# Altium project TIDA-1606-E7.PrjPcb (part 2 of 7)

## Sheet TIDA-1606-EMI-Protection-E7-.SchDoc
size 431 x 279 mm; Date: Not shown in title block; ApprovedBy: Not shown in title block; CheckedBy: Not shown in title block; Author: Not shown in title block; CompanyName: Not shown in title block; Engineer: Not shown in title block; Organization: Not shown in title block; Address1: Not shown in title block; Address2: Not shown in title block; Address3: Not shown in title block; Address4: Not shown in title block; DocumentNumber: 4; Revision: Use project parameter SCH_Rev; SheetNumber: 4; SheetTotal: 16; PageSetup: Record=PageOptions¦CenterHorizontal=True¦CenterVertical=True¦PrintScale=1.00¦XCorrection=1.00¦YCorrection=1.00¦PrintKind=0¦BorderSize=5000000¦LeftOffset=0¦BottomOffset=0¦Orientation=2¦PaperLength=1000¦PaperWidth=1000¦Scale=100¦PaperSource=15¦PrintQuality=600¦MediaType=1¦DitherType=10¦PaperKind=Letter¦PrintScaleMode=1
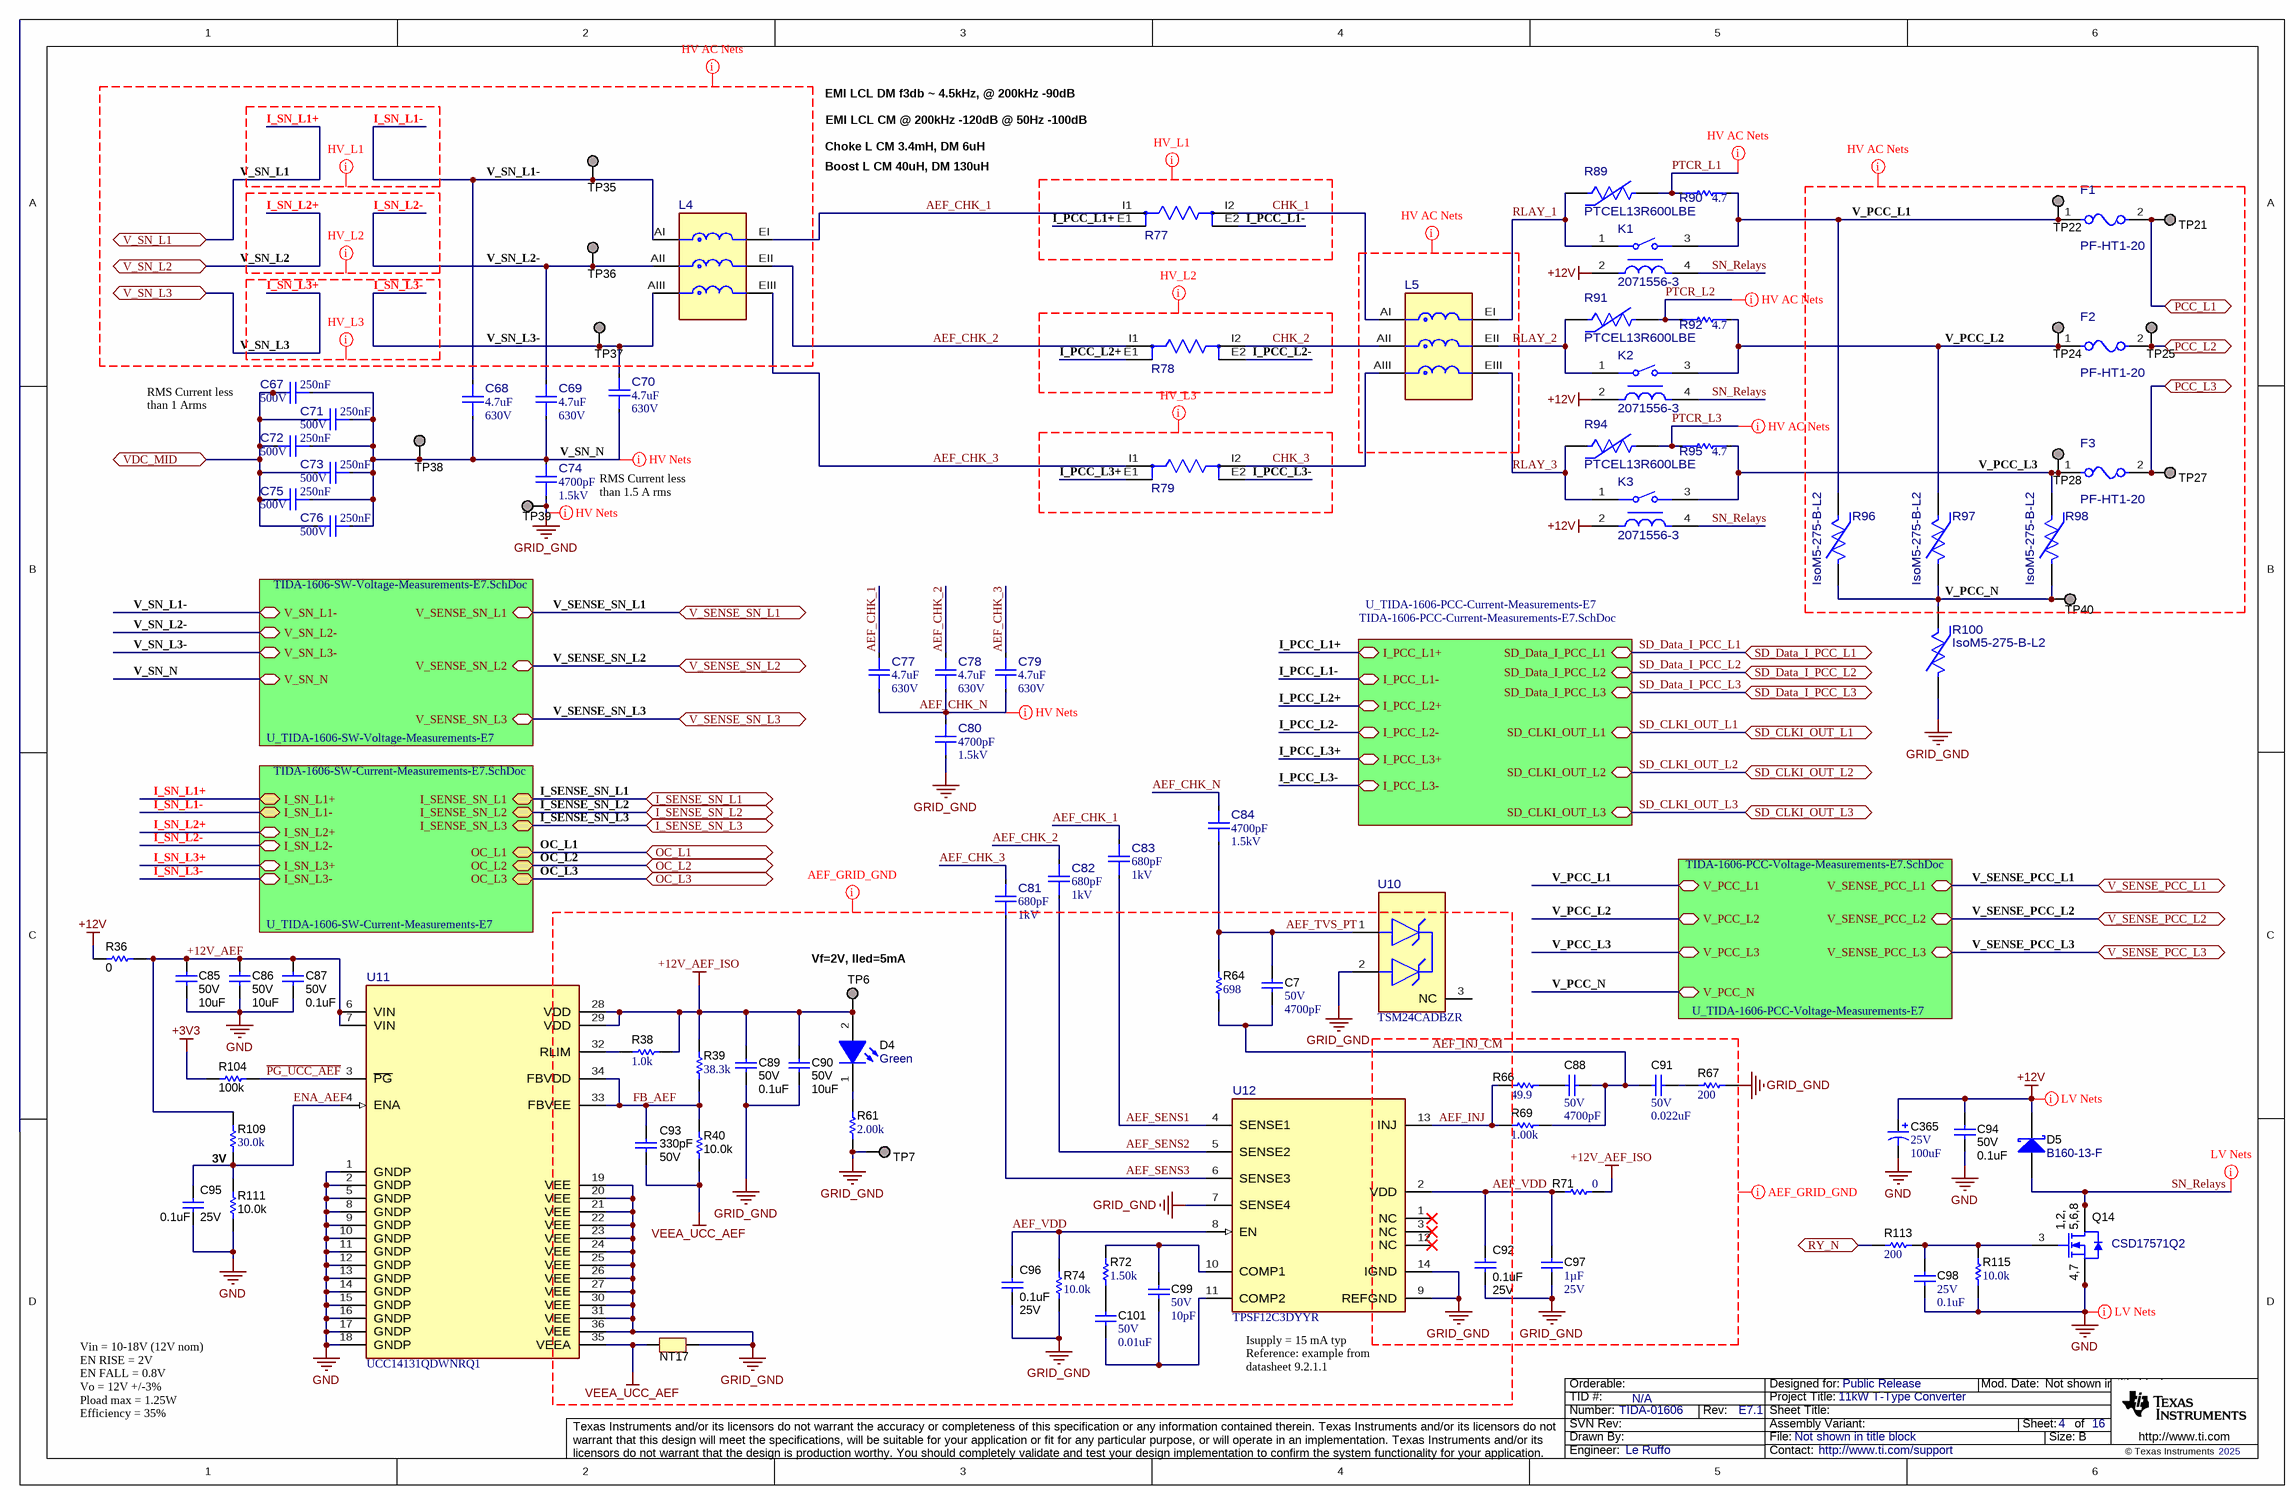
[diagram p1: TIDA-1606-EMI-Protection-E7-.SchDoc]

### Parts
C7  VDC_V: 50V  ValueDisplayed: 4700pF  [0402]  (hidden comment: GRM155R71H472KA01D)
C67  ValueDisplayed: 250nF  VDC_V: 500V  [FP-B58043E5254M052_2220-MFG]  (hidden comment: B58043E5254M052)
C68  ValueDisplayed: 4.7uF  VDC_V: 630V  [FP-R523R447050P1M_RADIAL-MFG]  (hidden comment: R523R447050P1M)
C69  ValueDisplayed: 4.7uF  VDC_V: 630V  [FP-R523R447050P1M_RADIAL-MFG]  (hidden comment: R523R447050P1M)
C70  ValueDisplayed: 4.7uF  VDC_V: 630V  [FP-R523R447050P1M_RADIAL-MFG]  (hidden comment: R523R447050P1M)
C71  ValueDisplayed: 250nF  VDC_V: 500V  [FP-B58043E5254M052_2220-MFG]  (hidden comment: B58043E5254M052)
C72  ValueDisplayed: 250nF  VDC_V: 500V  [FP-B58043E5254M052_2220-MFG]  (hidden comment: B58043E5254M052)
C73  ValueDisplayed: 250nF  VDC_V: 500V  [FP-B58043E5254M052_2220-MFG]  (hidden comment: B58043E5254M052)
C74  ValueDisplayed: 4700pF  VDC_V: 1.5kV  [FP-R413F147050T1K_RADIAL-MFG]  (hidden comment: R413F147050T1K)
C75  ValueDisplayed: 250nF  VDC_V: 500V  [FP-B58043E5254M052_2220-MFG]  (hidden comment: B58043E5254M052)
C76  ValueDisplayed: 250nF  VDC_V: 500V  [FP-B58043E5254M052_2220-MFG]  (hidden comment: B58043E5254M052)
C77  ValueDisplayed: 4.7uF  VDC_V: 630V  [FP-R523R447050P1M_RADIAL-MFG]  (hidden comment: R523R447050P1M)
C78  ValueDisplayed: 4.7uF  VDC_V: 630V  [FP-R523R447050P1M_RADIAL-MFG]  (hidden comment: R523R447050P1M)
C79  ValueDisplayed: 4.7uF  VDC_V: 630V  [FP-R523R447050P1M_RADIAL-MFG]  (hidden comment: R523R447050P1M)
C80  ValueDisplayed: 4700pF  VDC_V: 1.5kV  [FP-R413F147050T1K_RADIAL-MFG]  (hidden comment: R413F147050T1K)
C81  ValueDisplayed: 680pF  VDC_V: 1kV  [FP-DK1B3EA681K86RBH01_SMD2-MFG]  (hidden comment: DK1B3EA681K86RBH01)
C82  ValueDisplayed: 680pF  VDC_V: 1kV  [FP-DK1B3EA681K86RBH01_SMD2-MFG]  (hidden comment: DK1B3EA681K86RBH01)
C83  ValueDisplayed: 680pF  VDC_V: 1kV  [FP-DK1B3EA681K86RBH01_SMD2-MFG]  (hidden comment: DK1B3EA681K86RBH01)
C84  ValueDisplayed: 4700pF  VDC_V: 1.5kV  [FP-EVA86Q7UTF472KA01K_SMD2-MFG]  (hidden comment: EVA86Q7UTF472KA01K)
C85  VDC_V: 50V  ValueDisplayed: 10uF  [1206_180L]  (hidden comment: CL31B106KBHNNNE)
C86  VDC_V: 50V  ValueDisplayed: 10uF  [1206_180L]  (hidden comment: CL31B106KBHNNNE)
C87  VDC_V: 50V  ValueDisplayed: 0.1uF  [0402S]  (hidden comment: GCM155R71H104KE02D)
C88  VDC_V: 50V  ValueDisplayed: 4700pF  [0402]  (hidden comment: GRM155R71H472KA01D)
C89  VDC_V: 50V  ValueDisplayed: 0.1uF  [0402S]  (hidden comment: GCM155R71H104KE02D)
C90  VDC_V: 50V  ValueDisplayed: 10uF  [1206_180L]  (hidden comment: CL31B106KBHNNNE)
C91  VDC_V: 50V  ValueDisplayed: 0.022uF  [0402]  (hidden comment: GRM155R71H223KA12D)
C92  VDC_V: 25V  ValueDisplayed: 0.1uF  [0402S]  (hidden comment: GRM155R71E104KE14D)
C93  VDC_V: 50V  ValueDisplayed: 330pF  [0402S]  (hidden comment: CGA2B2X7R1H331K050BA)
C94  VDC_V: 50V  ValueDisplayed: 0.1uF  [0402S]  (hidden comment: GCM155R71H104KE02D)
C95  VDC_V: 25V  ValueDisplayed: 0.1uF  [0402S]  (hidden comment: GRM155R71E104KE14D)
C96  VDC_V: 25V  ValueDisplayed: 0.1uF  [0402S]  (hidden comment: GRM155R71E104KE14D)
C97  Cap_F: 1µF  VDC_V: 25V  [0603]  (hidden comment: CGA3E1X7R1E105M080AC)
C98  VDC_V: 25V  ValueDisplayed: 0.1uF  [0402]  (hidden comment: GRM155R71E104KE14D)
C99  VDC_V: 50V  ValueDisplayed: 10pF  [0402]  (hidden comment: CGA2B2C0G1H100D050BA)
C101  VDC_V: 50V  ValueDisplayed: 0.01uF  [0402]  (hidden comment: CGA2B3X7R1H103K050BB)
C365  VDC_V: 25V  ValueDisplayed: 100uF  [FM_630x1120]  (hidden comment: EEU-FM1E101)
D4  value Green  [WL-SMCW_GREEN]  (hidden comment: 150060VS75000)
D5  B160-13-F  [SMA]
F1  PF-HT1-20  [FP-PF-HT1-20_PTH_FUSE_38MM0_10MM3-MFG]
F2  PF-HT1-20  [FP-PF-HT1-20_PTH_FUSE_38MM0_10MM3-MFG]
F3  PF-HT1-20  [FP-PF-HT1-20_PTH_FUSE_38MM0_10MM3-MFG]
K1  2071556-3  [FP-2071556-3_PTH_RELAY_18MM2_10MM2-MFG]
K2  2071556-3  [FP-2071556-3_PTH_RELAY_18MM2_10MM2-MFG]
K3  2071556-3  [FP-2071556-3_PTH_RELAY_18MM2_10MM2-MFG]
L4  WK 3260A  [FP-WK 3260A_PTH6_41MM5_43MM5-MFG]  (value not drawn)
L5  WK 3260A  [FP-WK 3260A_PTH6_41MM5_43MM5-MFG]  (value not drawn)
NT17  Net-Tie  [Net-Tie7milsWide_20milsLong]  (value not drawn)  (net tie, no BOM)
Q14  CSD17571Q2  [DQK0006C]
R36  ValueDisplayed: 0  [0603L]  (hidden comment: RCS06030000Z0EA)
R38  ValueDisplayed: 1.0k  [0402]  (hidden comment: ERJ-2GEJ102X)
R39  ValueDisplayed: 38.3k  [0402]  (hidden comment: CRCW040238K3FKED)
R40  ValueDisplayed: 10.0k  [0402S]  (hidden comment: MCS0402MD1002BE100)
R61  ValueDisplayed: 2.00k  [0402]  (hidden comment: ERJ-2RKF2001X)
R64  ValueDisplayed: 698  [0402]  (hidden comment: ERJ-2RKF6980X)
R66  ValueDisplayed: 49.9  [0402L]  (hidden comment: ERJ-2RKF49R9X)
R67  ValueDisplayed: 200  [0402]  (hidden comment: CRCW0402200RJNED)
R69  ValueDisplayed: 1.00k  [0402]  (hidden comment: ERJ-2RKF1001X)
R71  ValueDisplayed: 0  [0402L]  (hidden comment: RC0402JR-070RL)
R72  ValueDisplayed: 1.50k  [0402]  (hidden comment: ERJ-2RKF1501X)
R74  ValueDisplayed: 10.0k  [0402]  (hidden comment: CRCW040210K0FKED)
R77  WSKW06122L000FEA  [FP-WSKW06122L000FEA_0612-MFG]  (value not drawn)
R78  WSKW06122L000FEA  [FP-WSKW06122L000FEA_0612-MFG]  (value not drawn)
R79  WSKW06122L000FEA  [FP-WSKW06122L000FEA_0612-MFG]  (value not drawn)
R89  PTCEL13R600LBE  [FP-PTCEL13R600LBE_RADIAL-MFG]
R90  value 4.7  [FP-UPR25J4R7CT_2512-MFG]  (hidden comment: UPR25J4R7CT)
R91  PTCEL13R600LBE  [FP-PTCEL13R600LBE_RADIAL-MFG]
R92  value 4.7  [FP-UPR25J4R7CT_2512-MFG]  (hidden comment: UPR25J4R7CT)
R94  PTCEL13R600LBE  [FP-PTCEL13R600LBE_RADIAL-MFG]
R95  value 4.7  [FP-UPR25J4R7CT_2512-MFG]  (hidden comment: UPR25J4R7CT)
R96  IsoM5-275-B-L2  [FP-IsoM5-275-B-L2_RADIAL-MFG]
R97  IsoM5-275-B-L2  [FP-IsoM5-275-B-L2_RADIAL-MFG]
R98  IsoM5-275-B-L2  [FP-IsoM5-275-B-L2_RADIAL-MFG]
R100  IsoM5-275-B-L2  [FP-IsoM5-275-B-L2_RADIAL-MFG]
R104  ValueDisplayed: 100k  [0402S]  (hidden comment: ERJ-2GEJ104X)
R109  ValueDisplayed: 30.0k  [0402]  (hidden comment: CRCW040230K0FKED)
R111  ValueDisplayed: 10.0k  [0402S]  (hidden comment: MCS0402MD1002BE100)
R113  ValueDisplayed: 200  [0402]  (hidden comment: CRCW0402200RJNED)
R115  ValueDisplayed: 10.0k  [0402]  (hidden comment: CRCW040210K0FKED)
TP6  TP_SM_1MM  [TP_SM_1MM]  (value not drawn)  (no BOM)
TP7  S2751-46R  [Harwin_S2751-46R]  (value not drawn)
TP21  S2751-46R  [Harwin_S2751-46R]  (value not drawn)
TP22  S2751-46R  [Harwin_S2751-46R]  (value not drawn)
TP24  S2751-46R  [Harwin_S2751-46R]  (value not drawn)
TP25  S2751-46R  [Harwin_S2751-46R]  (value not drawn)
TP27  S2751-46R  [Harwin_S2751-46R]  (value not drawn)
TP28  S2751-46R  [Harwin_S2751-46R]  (value not drawn)
TP35  S2751-46R  [Harwin_S2751-46R]  (value not drawn)
TP36  S2751-46R  [Harwin_S2751-46R]  (value not drawn)
TP37  S2751-46R  [Harwin_S2751-46R]  (value not drawn)
TP38  S2751-46R  [Harwin_S2751-46R]  (value not drawn)
TP39  S2751-46R  [Harwin_S2751-46R]  (value not drawn)
TP40  S2751-46R  [Harwin_S2751-46R]  (value not drawn)
U10  TSM24CADBZR  [DBZ0003A-MFG]
U11  UCC14131QDWNRQ1  [DWJ0036A-MFG]
U12  TPSF12C3DYYR  [DYY0014A-MFG]

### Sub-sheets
U_TIDA-1606-PCC-Current-Measurements-E7 = TIDA-1606-PCC-Current-Measurements-E7.SchDoc: I_PCC_L1+ (bidir), I_PCC_L1- (bidir), I_PCC_L2+ (bidir), I_PCC_L2- (bidir), I_PCC_L3+ (bidir), I_PCC_L3- (bidir), SD_Data_I_PCC_L1 (bidir), SD_Data_I_PCC_L2 (bidir), SD_Data_I_PCC_L3 (bidir), SD_CLKI_OUT_L1 (bidir), SD_CLKI_OUT_L2 (bidir), SD_CLKI_OUT_L3 (bidir)
U_TIDA-1606-PCC-Voltage-Measurements-E7 = TIDA-1606-PCC-Voltage-Measurements-E7.SchDoc: V_PCC_L1 (bidir), V_PCC_N (bidir), V_PCC_L2 (bidir), V_PCC_L3 (bidir), V_SENSE_PCC_L1 (bidir), V_SENSE_PCC_L2 (bidir), V_SENSE_PCC_L3 (bidir)
U_TIDA-1606-SW-Current-Measurements-E7 = TIDA-1606-SW-Current-Measurements-E7.SchDoc: I_SENSE_SN_L1 (bidir), I_SENSE_SN_L2 (bidir), I_SENSE_SN_L3 (bidir), I_SN_L1+ (bidir), I_SN_L1- (bidir), I_SN_L2+ (bidir), I_SN_L2- (bidir), I_SN_L3+ (bidir), I_SN_L3- (bidir), OC_L1 (bidir), OC_L2 (bidir), OC_L3 (bidir)
U_TIDA-1606-SW-Voltage-Measurements-E7 = TIDA-1606-SW-Voltage-Measurements-E7.SchDoc: V_SN_L1- (bidir), V_SN_N (bidir), V_SN_L2- (bidir), V_SN_L3- (bidir), V_SENSE_SN_L1 (bidir), V_SENSE_SN_L2 (bidir), V_SENSE_SN_L3 (bidir)

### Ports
I_SENSE_SN_L1 (bidir), I_SENSE_SN_L2 (bidir), I_SENSE_SN_L3 (bidir), OC_L1 (bidir), OC_L2 (bidir), OC_L3 (bidir), PCC_L1 (bidir), PCC_L2 (bidir), PCC_L3 (bidir), RY_N (bidir), SD_CLKI_OUT_L1 (bidir), SD_CLKI_OUT_L2 (bidir), SD_CLKI_OUT_L3 (bidir), SD_Data_I_PCC_L1 (bidir), SD_Data_I_PCC_L2 (bidir), SD_Data_I_PCC_L3 (bidir), V_SENSE_PCC_L1 (bidir), V_SENSE_PCC_L2 (bidir), V_SENSE_PCC_L3 (bidir), V_SENSE_SN_L1 (bidir), V_SENSE_SN_L2 (bidir), V_SENSE_SN_L3 (bidir), V_SN_L1 (bidir), V_SN_L2 (bidir), V_SN_L3 (bidir), VDC_MID (bidir)

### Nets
+3V3: R104.1
+12V: C94.1 C365.1(+) D5.1(K) K1.2 K2.2 K3.2 R36.2
+12V_AEF_ISO: C89.1 C90.1 D4.2(A) R38.2 R39.2 R71.2 TP6.1 U11.28(VDD) U11.29(VDD)
GND: C85.2 C86.2 C87.2 C94.2 C95.2 C98.2 C365.2(-) Q14.4(S) Q14.7(S) R111.1 R115.1 U11.1(GNDP) U11.2(GNDP) U11.5(GNDP) U11.8(GNDP) U11.9(GNDP) U11.10(GNDP) U11.11(GNDP) U11.12(GNDP) U11.13(GNDP) U11.14(GNDP) U11.15(GNDP) U11.16(GNDP) U11.17(GNDP) U11.18(GNDP)
GRID_GND: C74.1 C80.1 C89.2 C90.2 C92.2 C96.2 C97.2 NT17.1 R61.1 R67.2 R74.1 R100.1 TP7.1 TP39.1 U10.2(2_IO) U11.19(VEE) U11.20(VEE) U11.21(VEE) U11.22(VEE) U11.23(VEE) U11.24(VEE) U11.25(VEE) U11.26(VEE) U11.27(VEE) U11.30(VEE) U11.31(VEE) U11.36(VEE) U12.7(SENSE4) U12.9(REFGND) U12.14(IGND)
VDC_MID: C67.2 C71.2 C72.2 C73.2 C75.2 C76.2 ; port VDC_MID
VEEA_UCC_AEF: C93.2 NT17.2 R40.1 U11.35(VEEA)
+12V_AEF: C85.1 C86.1 C87.1 R36.1 R109.2 U11.6(VIN) U11.7(VIN)
~{PG_UCC_AEF}: R104.2 U11.3(~{PG})
AEF_CHK_1: C77.2 C83.2 L4.EI R77.I1
AEF_CHK_2: C78.2 C82.2 L4.EII R78.I1
AEF_CHK_3: C79.2 C81.2 L4.EIII R79.I1
AEF_CHK_N: C77.1 C78.1 C79.1 C80.2 C84.2
AEF_INJ: R66.1 R69.1 U12.13(INJ)
AEF_INJ_CM: C7.2 C88.2 C91.2 R64.1 R69.2
AEF_SENS1: C83.1 U12.4(SENSE1)
AEF_SENS2: C82.1 U12.5(SENSE2)
AEF_SENS3: C81.1 U12.6(SENSE3)
AEF_TVS_PT: C7.1 C84.1 R64.2 U10.1(1_IO)
AEF_VDD: C92.1 C96.1 C97.1 R71.1 R74.2 U12.2(VDD) U12.8(EN)
CHK_1: L5.AI R77.I2
CHK_2: L5.AII R78.I2
CHK_3: L5.AIII R79.I2
ENA_AEF: C95.1 R109.1 R111.2 U11.4(ENA)
FB_AEF: C93.1 R39.1 R40.2 U11.33(FBVEE) U11.34(FBVDD)
I_PCC_L1+: R77.E1 ; sheet U_TIDA-1606-PCC-Current-Measurements-E7/I_PCC_L1+
I_PCC_L1-: R77.E2 ; sheet U_TIDA-1606-PCC-Current-Measurements-E7/I_PCC_L1-
I_PCC_L2+: R78.E1 ; sheet U_TIDA-1606-PCC-Current-Measurements-E7/I_PCC_L2+
I_PCC_L2-: R78.E2 ; sheet U_TIDA-1606-PCC-Current-Measurements-E7/I_PCC_L2-
I_PCC_L3+: R79.E1 ; sheet U_TIDA-1606-PCC-Current-Measurements-E7/I_PCC_L3+
I_PCC_L3-: R79.E2 ; sheet U_TIDA-1606-PCC-Current-Measurements-E7/I_PCC_L3-
I_SENSE_SN_L1: port I_SENSE_SN_L1, sheet U_TIDA-1606-SW-Current-Measurements-E7/I_SENSE_SN_L1
I_SENSE_SN_L2: port I_SENSE_SN_L2, sheet U_TIDA-1606-SW-Current-Measurements-E7/I_SENSE_SN_L2
I_SENSE_SN_L3: port I_SENSE_SN_L3, sheet U_TIDA-1606-SW-Current-Measurements-E7/I_SENSE_SN_L3
I_SN_L1+: port V_SN_L1, sheet U_TIDA-1606-SW-Current-Measurements-E7/I_SN_L1+  [also labelled V_SN_L1]
I_SN_L1-: C68.2 L4.AI TP35.1 ; sheet U_TIDA-1606-SW-Voltage-Measurements-E7/V_SN_L1-, sheet U_TIDA-1606-SW-Current-Measurements-E7/I_SN_L1-  [also labelled V_SN_L1-]
I_SN_L2+: port V_SN_L2, sheet U_TIDA-1606-SW-Current-Measurements-E7/I_SN_L2+  [also labelled V_SN_L2]
I_SN_L2-: C69.2 L4.AII TP36.1 ; sheet U_TIDA-1606-SW-Voltage-Measurements-E7/V_SN_L2-, sheet U_TIDA-1606-SW-Current-Measurements-E7/I_SN_L2-  [also labelled V_SN_L2-]
I_SN_L3+: port V_SN_L3, sheet U_TIDA-1606-SW-Current-Measurements-E7/I_SN_L3+  [also labelled V_SN_L3]
I_SN_L3-: C70.2 L4.AIII TP37.1 ; sheet U_TIDA-1606-SW-Voltage-Measurements-E7/V_SN_L3-, sheet U_TIDA-1606-SW-Current-Measurements-E7/I_SN_L3-  [also labelled V_SN_L3-]
OC_L1: port OC_L1, sheet U_TIDA-1606-SW-Current-Measurements-E7/OC_L1
OC_L2: port OC_L2, sheet U_TIDA-1606-SW-Current-Measurements-E7/OC_L2
OC_L3: port OC_L3, sheet U_TIDA-1606-SW-Current-Measurements-E7/OC_L3
PCC_L1: F1.2 TP21.1 ; port PCC_L1
PCC_L2: F2.2 TP25.1 ; port PCC_L2
PCC_L3: F3.2 TP27.1 ; port PCC_L3
PTCR_L1: R89.2 R90.1
PTCR_L2: R91.2 R92.1
PTCR_L3: R94.2 R95.1
RLAY_1: K1.1 L5.EI R89.1
RLAY_2: K2.1 L5.EII R91.1
RLAY_3: K3.1 L5.EIII R94.1
RY_N: R113.1 ; port RY_N
SD_CLKI_OUT_L1: port SD_CLKI_OUT_L1, sheet U_TIDA-1606-PCC-Current-Measurements-E7/SD_CLKI_OUT_L1
SD_CLKI_OUT_L2: port SD_CLKI_OUT_L2, sheet U_TIDA-1606-PCC-Current-Measurements-E7/SD_CLKI_OUT_L2
SD_CLKI_OUT_L3: port SD_CLKI_OUT_L3, sheet U_TIDA-1606-PCC-Current-Measurements-E7/SD_CLKI_OUT_L3
SD_Data_I_PCC_L1: port SD_Data_I_PCC_L1, sheet U_TIDA-1606-PCC-Current-Measurements-E7/SD_Data_I_PCC_L1
SD_Data_I_PCC_L2: port SD_Data_I_PCC_L2, sheet U_TIDA-1606-PCC-Current-Measurements-E7/SD_Data_I_PCC_L2
SD_Data_I_PCC_L3: port SD_Data_I_PCC_L3, sheet U_TIDA-1606-PCC-Current-Measurements-E7/SD_Data_I_PCC_L3
SN_Relays: D5.2(A) K1.4 K2.4 K3.4 Q14.1(D) Q14.2(D) Q14.5(D) Q14.6(D) Q14.8(D)
V_PCC_L1: F1.1 K1.3 R90.2 R96.2 TP22.1 ; sheet U_TIDA-1606-PCC-Voltage-Measurements-E7/V_PCC_L1
V_PCC_L2: F2.1 K2.3 R92.2 R97.2 TP24.1 ; sheet U_TIDA-1606-PCC-Voltage-Measurements-E7/V_PCC_L2
V_PCC_L3: F3.1 K3.3 R95.2 R98.2 TP28.1 ; sheet U_TIDA-1606-PCC-Voltage-Measurements-E7/V_PCC_L3
V_PCC_N: R96.1 R97.1 R98.1 R100.2 TP40.1 ; sheet U_TIDA-1606-PCC-Voltage-Measurements-E7/V_PCC_N
V_SENSE_PCC_L1: port V_SENSE_PCC_L1, sheet U_TIDA-1606-PCC-Voltage-Measurements-E7/V_SENSE_PCC_L1
V_SENSE_PCC_L2: port V_SENSE_PCC_L2, sheet U_TIDA-1606-PCC-Voltage-Measurements-E7/V_SENSE_PCC_L2
V_SENSE_PCC_L3: port V_SENSE_PCC_L3, sheet U_TIDA-1606-PCC-Voltage-Measurements-E7/V_SENSE_PCC_L3
V_SENSE_SN_L1: port V_SENSE_SN_L1, sheet U_TIDA-1606-SW-Voltage-Measurements-E7/V_SENSE_SN_L1
V_SENSE_SN_L2: port V_SENSE_SN_L2, sheet U_TIDA-1606-SW-Voltage-Measurements-E7/V_SENSE_SN_L2
V_SENSE_SN_L3: port V_SENSE_SN_L3, sheet U_TIDA-1606-SW-Voltage-Measurements-E7/V_SENSE_SN_L3
V_SN_N: C67.1 C68.1 C69.1 C70.1 C71.1 C72.1 C73.1 C74.2 C75.1 C76.1 TP38.1 ; sheet U_TIDA-1606-SW-Voltage-Measurements-E7/V_SN_N
NetC88_1: C88.1 R66.2
NetC91_1: C91.1 R67.1
NetC98_1: C98.1 Q14.3(G) R113.2 R115.2
NetC99_1: C99.1 R72.2 U12.10(COMP1)
NetC99_2: C99.2 C101.2 U12.11(COMP2)
NetC101_1: C101.1 R72.1
NetD4_1: D4.1(K) R61.2
NetR38_1: R38.1 U11.32(RLIM)

Not connected (* = marked no-connect by the designer): U10 3(NC); U12 1(NC)* 3(NC)* 12(NC)*

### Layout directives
net class HV_Nets; net class HV_AC1: AEF_CHK_N, GRID_GND, V_SN_N
net class HV_AC1: I_SN_L1+, I_SN_L1-, I_SN_L2+, I_SN_L2-, I_SN_L3+, I_SN_L3-, PTCR_L1, PTCR_L2, PTCR_L3, RLAY_2, V_SN_L1, V_SN_L1-, V_SN_L2, V_SN_L2-, V_SN_L3, V_SN_L3-
net class HV_L1: CHK_1, I_PCC_L1+, I_PCC_L1-, I_SN_L1+, I_SN_L1-, I_SN_L2+, I_SN_L2-, I_SN_L3+, I_SN_L3-, V_SN_L1, V_SN_L1-, V_SN_L2, V_SN_L2-, V_SN_L3, V_SN_L3-
net class HV_AC1; net class HV_Nets: V_PCC_L1, V_PCC_L2, V_PCC_L3, V_PCC_N
net class LV Nets: +12V, GND, SN_Relays
net class HV_L2: CHK_2, I_PCC_L2+, I_PCC_L2-, I_SN_L1+, I_SN_L1-, I_SN_L2+, I_SN_L2-, I_SN_L3+, I_SN_L3-, V_SN_L1, V_SN_L1-, V_SN_L2, V_SN_L2-, V_SN_L3, V_SN_L3-
net class HV_L3: CHK_3, I_PCC_L3+, I_PCC_L3-, I_SN_L1+, I_SN_L1-, I_SN_L2+, I_SN_L2-, I_SN_L3+, I_SN_L3-, V_SN_L1, V_SN_L1-, V_SN_L2, V_SN_L2-, V_SN_L3, V_SN_L3-
net class AEF_GRID_GND; net class HV_AC1: +12V_AEF_ISO, AEF_INJ, AEF_INJ_CM, AEF_SENS1, AEF_SENS2, AEF_SENS3, AEF_TVS_PT, AEF_VDD, FB_AEF, GRID_GND, VEEA_UCC_AEF

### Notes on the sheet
- EMI LCL DM f3db ~ 4.5kHz, @ 200kHz -90dB
- Choke L CM 3.4mH, DM 6uH
- Boost L CM 40uH, DM 130uH
- EMI LCL CM @ 200kHz -120dB @ 50Hz -100dB
- RMS Current less than 1 Arms
- RMS Current less than 1.5 A rms
- (near TP6) Vf=2V, Iled=5mA
- (near R109) 3V
- Vin = 10-18V (12V nom)
  EN RISE = 2V
  EN FALL = 0.8V
  Vo = 12V +/-3%
  Pload max = 1.25W
  Efficiency = 35%
- (near U12) Isupply = 15 mA typ
  Reference: example from datasheet 9.2.1.1

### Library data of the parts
C7 C88 = CMP-0006692-2: CAP, CERM, 4700 pF, 50 V, +/- 10%, X7R, 0402; Manufacturer: MuRata; TaMin_C: -55°C; Polarized: N; SizeAreaWB_mm2: 3; Value1: Unknown; U/M: EA; Value: 4700pF; TaMax_C: 125°C; SizeZ_mm: 0.6; SizeX_mm: 1; SizeY_mm: 0.5; Cap_F: 4.7nF; AEC Category: Q200
C67 C71-C73 C75 C76 = CMP-0098327-1: 0.25 µF ±20% 500V Ceramic Capacitor 2220 (5750 Metric); Manufacturer: TDK; AEC Qualified: No; SizeZ_mm: 1.6mm; Value: 250nF
C68-C70 C77-C79 = CMP-0098409-1: 4.7 µF Film Capacitor 310V 630V Polypropylene (PP), Metallized Radial; Manufacturer: KEMET; AEC Grade: Grade 2; AEC Qualified: Yes; Cap_F: 4.7µF; SizeZ_mm: 28.1mm; Tolerance_%: 20%; VAC_X: X2; Value: 4.7µF
C74 C80 = CMP-0098408-1: Cap Film 0.0047uF 1500V PP 10% Dipped 10mm 125°C Bulk; Manufacturer: KEMET; AEC Grade: Grade 1; AEC Qualified: Yes; Cap_F: 4.7nF; SizeZ_mm: 11.1mm; VAC: 300V; VAC_Y: Y2; Value: 4.7nF
C81-C83 = CMP-0122968-1: 680pF ±10% 300VAC Ceramic Capacitor B Nonstandard SMD; Manufacturer: Murata; AEC Qualified: No; SizeZ_mm: 2.5mm; Voltage Ac Rating X: 440V; Voltage Ac Rating Y: 300V
C84 = CMP-0122969-1: 4700 pF ±10% 305VAC Ceramic Capacitor U2J Nonstandard SMD; Manufacturer: Murata; AEC Grade: Grade 1; AEC Qualified: Yes; Cap_F: 4.7nF; SizeZ_mm: 4.2mm; TempCo: -630/-1097ppm/°C; VAC: 305V; Value: 4.7nF
C85 C86 C90 = CMP-0008802-2: CAP, CERM, 10 uF, 50 V, +/- 10%, X7R, 1206; Manufacturer: Samsung; TaMin_C: -55°C; Polarized: N; SizeAreaWB_mm2: 10.92; Value1: Unknown; U/M: EA; Value: 10uF; TaMax_C: 125°C; SizeZ_mm: 1.8; SizeX_mm: 3.2; SizeY_mm: 1.6; Cap_Case: 1206; SizeArea_mm2: 5.12; Cap_F: 10µF; AEC Category: Q200
C87 C89 C94 = CMP-0006356-2: CAP, CERM, 0.1 uF, 50 V, +/- 10%, X7R, AEC-Q200 Grade 1, 0402; Manufacturer: MuRata; TaMin_C: -55°C; Polarized: N; SizeAreaWB_mm2: 3; Value1: Unknown; U/M: EA; Value: 0.1uF; TaMax_C: 125°C; SizeZ_mm: 0.6; SizeX_mm: 1; SizeY_mm: 0.5; Cap_Case: 0402; AEC Qualified: Y; Cap_F: 100nF; AEC Category: Q200
C91 = CMP-0006684-2: CAP, CERM, 0.022 uF, 50 V, +/- 10%, X7R, 0402; Manufacturer: MuRata; TaMin_C: -55°C; Polarized: N; SizeAreaWB_mm2: 3; Value1: Unknown; U/M: EA; TaMax_C: 125°C; SizeZ_mm: 0.6; SizeX_mm: 1; SizeY_mm: 0.5; Cap_F: 22nF; AEC Category: Q200
C92 C95 C96 = CMP-0006659-2: CAP, CERM, 0.1 uF, 25 V, +/- 10%, X7R, 0402; Manufacturer: MuRata; TaMin_C: -55°C; Polarized: N; SizeAreaWB_mm2: 3; Value1: Unknown; U/M: EA; Value: 0.1uF; TaMax_C: 125°C; SizeZ_mm: 0.6; SizeX_mm: 1; SizeY_mm: 0.5; Cap_Case: 0402; Cap_F: 100nF; AEC Category: Q200
C93 = CMP-0006318-2: CAP, CERM, 330 pF, 50 V, +/- 10%, X7R, AEC-Q200 Grade 1, 0402; Manufacturer: TDK; TaMin_C: -55°C; ESR_ohm: 6.53276; Polarized: N; SizeAreaWB_mm2: 3; Value1: 6.53276 ohm; U/M: EA; Value: 330pF; TaMax_C: 125°C; SizeZ_mm: 0.6; SizeX_mm: 1; SizeY_mm: 0.5; Cap_Case: 0402; AEC Qualified: Y; IRMS_A: 2.12649dA; AEC Category: Q200
C97 = CMP-0082113-1: CAP, CERM, 1 µF, 25 V,+/- 20%, X7R, AEC-Q200 Grade 1, 0603; Manufacturer: TDK; SizeAreaWB_mm2: 4.68; SizeArea_mm2: 1.28; AEC Qualified: Y; AEC Category: Q200; Value: 1uF; TaMax_C: 125°C; SizeZ_mm: 1; Polarized: N; TaMin_C: -55°C; SizeY_mm: 0.8; U/M: EA; SizeX_mm: 1.6
C98 = CMP-0006659-2: CAP, CERM, 0.1 uF, 25 V, +/- 10%, X7R, 0402; Manufacturer: MuRata; TaMin_C: -55°C; Polarized: N; SizeAreaWB_mm2: 3; Value1: Unknown; U/M: EA; Value: 0.1uF; TaMax_C: 125°C; SizeZ_mm: 0.6; SizeX_mm: 1; SizeY_mm: 0.5; Cap_F: 100nF; AEC Category: Q200
C99 = CMP-0006307-2: CAP, CERM, 10 pF, 50 V, +/- 5%, C0G/NP0, AEC-Q200 Grade 1, 0402; Manufacturer: TDK; TaMin_C: -55°C; Polarized: N; SizeAreaWB_mm2: 3; Value1: Unknown; U/M: EA; Value: 10pF; TaMax_C: 125°C; SizeZ_mm: 0.6; SizeX_mm: 1; SizeY_mm: 0.5; AEC Qualified: Y; AEC Category: Q200
C101 = CMP-0006324-2: CAP, CERM, 0.01 uF, 50 V, +/- 10%, X7R, AEC-Q200 Grade 1, 0402; Manufacturer: TDK; TaMin_C: -55°C; ESR_ohm: 0.333065; Polarized: N; SizeAreaWB_mm2: 3; Value1: 0.333065 ohm; U/M: EA; Value: 0.01uF; TaMax_C: 125°C; SizeZ_mm: 0.6; SizeX_mm: 1; SizeY_mm: 0.5; AEC Qualified: Y; Cap_F: 10nF; IRMS_A: 323.373mA; AEC Category: Q200
C365 = CMP-0010339-1: CAP, AL, 100 uF, 25 V, +/- 20%, 0.13 ohm, TH; Manufacturer: Panasonic; TaMin_C: -40°C; ESR_ohm: 0.13; Polarized: Y; SizeAreaWB_mm2: 68.89; U/M: EA; Value: 100uF; TaMax_C: 105°C; SizeZ_mm: 12.7; SizeX_mm: 6.3; Cap_Case: 6.3x11.2; SizeArea_mm2: 39.69; CompType: Capacitor; AEC Qualified: N; Cap_F: 100µF; IRMS_A: 455mA; AEC Category: Q200
D4 = CMP-0002894-2: LED, Green, SMD; Manufacturer: Wurth Elektronik; Type: AlInGaP; Value2: 2V; Io_A: 20mA; Value1: W
D5 = CMP-0028389-2: Diode, Schottky, 60 V, 1 A, SMA; Manufacturer: Diodes Inc.; Green_Lifecycle: Not Set; SizeAreaWB_mm2: 37.3428; Green_REACh: Incomplete; TJmax_C: 150°C; AEC Category: Q101; SizeZ_mm: 2.87; RJC_CperW: 20; Io_A: 1A; SizeArea_mm2: 16.3228; Vf_V: 700mV; Value2: 0.7V; SizeY_mm: 2.92; Vr_V: 60V; SizeX_mm: 5.59; Value: 60V
F1-F3 = CMP-0097107-1: Fuse Cartridge 20A 600V Cartridge 38 X 10.3 X 11.7mm; Manufacturer: Bourns; Fuse Speed: Medium; Interrupt_AC: 150kA; Fuse Interrupt Dc Current: 50000A; Res_ohm: 0.004905Ω; SizeZ_mm: 12mm; Fuse I2T: 206.48A2Sec; Interrupt_DC: 50kA; AEC Qualified: No
K1-K3 = CMP-0042926-1: General Purpose Relay SPST-NO (1 Form A) 12VDC Coil Through Hole; Manufacturer: TE Connectivity; Coil Power_W: 450mW; Coil Type: Non-Latching; Coil Voltage_VDC: 12V; Contact Rating_A: 16A; SizeZ_mm: 15.3mm; AEC Qualified: No; Coil Resistance: 320Ω; TaMax_C: +85°C; TaMin_C: -40°C
L4 L5 = CMP-0098429-2: Common Mode Choke; Manufacturer: Kaschke Components; AEC Qualified: No; DCR_ohm: 10m; Imax_A: 26A; Ind_H: 3mH; SizeZ_mm: 36mm; Test Frequency: 10kHz; Tolerance_%: 30%
NT17 = CMP-0078142-6: Single point connection between nets.
Q14 = CMP-0000585-1: MOSFET, N-CH, 30 V, 22 A, DQK0006C (WSON-6); Alternate Manufacturer: None; Manufacturer: Texas Instruments; SizeZ_mm: 0.8; ChType: N; Value2: 2.4 nC; Value1: 0.02; VdsMax_V: 30V; SizeX_mm: 2; Vgs_V: 20V; Value: 30V; Rdson45_ohm: 0.029; SizeArea_mm2: 4; AEC Category: Q101; IdsMax_A: 22A; SizeAreaWB_mm2: 9; U/M: EA; QgTyp_nC: 2.4
R36 = CMP-0081973-1: RES, 0, 0%, 0.25 W, AEC-Q200 Grade 0, 0603; Manufacturer: Vishay-Dale; SizeAreaWB_mm2: 4.68; SizeArea_mm2: 1.28; AEC Qualified: Y; AEC Category: Q200; Value: 0; SizeZ_mm: 1; SizeY_mm: 0.8; Power_W: 250mW; Value2: 0.25W; SizeX_mm: 1.6
R38 = CMP-0078193-1: RES, 1.0 k, 5%, 0.1 W, AEC-Q200 Grade 0, 0402; Manufacturer: Panasonic; Value_Code: 1k00; SizeArea_mm2: 0.5; AEC Qualified: Y; AEC Category: Q200; Res_ohm: 1k; Value: 1.0k; SizeZ_mm: 0.6; Green_REACh: Passed; EIA_Code: E24; TempCo: 200 ppm/C; AEC Grade: 0; Power_W: 100mW; VDC_V: 50V; Value2: 0.1W; Green_Lifecycle: Active; U/M: EA; SizeX_mm: 1
R39 = CMP-0026323-2: RES, 38.3 k, 1%, 0.063 W, AEC-Q200 Grade 0, 0402; Manufacturer: Vishay-Dale; Power_W: 63mW; TempCo: 100 ppm/C; Value_Code: 38k3; Value: 38.3k; EIA_Code: E96; SizeX_mm: 1; SizeY_mm: 0.5; SizeZ_mm: 0.6; Value2: 0.063W; AEC Qualified: Y; VDC_V: 50V; AEC Category: Q200; AEC Grade: 0
R40 R111 = CMP-0077124-1: RES, 10.0 k, 0.1%, 0.1 W, AEC-Q200 Grade 0, 0402; Manufacturer: Vishay/Beyschlag; Value_Code: 10k0; SizeArea_mm2: 0.5; AEC Qualified: Y; AEC Category: Q200; Res_ohm: 10k; Value: 10.0k; SizeZ_mm: 0.6; EIA_Code: E192; TempCo: 25 ppm/C; AEC Grade: 0; Power_W: 100mW; VDC_V: 50V; Value2: 0.1W; U/M: EA; SizeX_mm: 1.0
R61 = CMP-0026676-1: RES, 2.00 k, 1%, 0.1 W, AEC-Q200 Grade 0, 0402; Manufacturer: Panasonic; Power_W: 100mW; TempCo: 100 ppm/C; Value_Code: 2k00; U/M: EA; Value: 2.00k; EIA_Code: E96; Res_ohm: 2k; SizeX_mm: 1; SizeY_mm: 0.5; SizeZ_mm: 0.6; Value2: 0.1W; AEC Qualified: Y; VDC_V: 50V; AEC Grade: 0; AEC Category: Q200
R64 = CMP-0026708-1: RES, 698, 1%, 0.1 W, 0402; Manufacturer: Panasonic; Power_W: 100mW; TempCo: 100 ppm/C; Value_Code: 698R; U/M: EA; Value: 698; EIA_Code: E96; SizeX_mm: 1; SizeY_mm: 0.5; SizeZ_mm: 0.6; Value2: 0.1W; VDC_V: 50V; AEC Category: Q200
R66 = CMP-0026703-1: RES, 49.9, 1%, 0.1 W, AEC-Q200 Grade 0, 0402; Manufacturer: Panasonic; Power_W: 100mW; TempCo: 100 ppm/C; Value_Code: 49R9; U/M: EA; Value: 49.9; EIA_Code: E96; SizeX_mm: 1; SizeY_mm: 0.5; SizeZ_mm: 0.6; Value2: 0.1W; AEC Qualified: Y; VDC_V: 50V; AEC Grade: 0; AEC Category: Q200
R67 R113 = CMP-0026874-3: RES, 200, 5%, 0.063 W, AEC-Q200 Grade 0, 0402; Manufacturer: Vishay-Dale; Power_W: 63mW; TempCo: 200 ppm/C; Value_Code: 200R; Value: 200; EIA_Code: E24; SizeX_mm: 1; SizeY_mm: 0.5; SizeZ_mm: 0.6; Value2: 0.063W; AEC Qualified: Y; VDC_V: 50V; AEC Category: Q200; AEC Grade: 0
R69 = CMP-0026657-1: RES, 1.00 k, 1%, 0.1 W, 0402; Manufacturer: Panasonic; Power_W: 100mW; TempCo: 100 ppm/C; Value_Code: 1k00; U/M: EA; Value: 1.00k; EIA_Code: E96; Res_ohm: 1k; SizeX_mm: 1; SizeY_mm: 0.5; SizeZ_mm: 0.6; Value2: 0.1W; VDC_V: 50V; AEC Category: Q200
R71 = CMP-0027004-2: RES, 0, 5%, 0.063 W, 0402; Manufacturer: Yageo America; Power_W: 63mW; TempCo: 200 ppm/C; Value_Code: 0000; U/M: EA; Value: 0; EIA_Code: E24; SizeX_mm: 1; SizeY_mm: 0.5; SizeZ_mm: 0.6; Value2: 0.063W; VDC_V: 50V; AEC Category: Q200
R72 = CMP-0026668-1: RES, 1.50 k, 1%, 0.1 W, AEC-Q200 Grade 0, 0402; Manufacturer: Panasonic; Power_W: 100mW; TempCo: 100 ppm/C; Value_Code: 1k50; U/M: EA; Value: 1.50k; EIA_Code: E96; Res_ohm: 1.5k; SizeX_mm: 1; SizeY_mm: 0.5; SizeZ_mm: 0.6; Value2: 0.1W; AEC Qualified: Y; VDC_V: 50V; AEC Grade: 0; AEC Category: Q200
R74 R115 = CMP-0025958-3: RES, 10.0 k, 1%, 0.063 W, AEC-Q200 Grade 0, 0402; Manufacturer: Vishay-Dale; Power_W: 63mW; TempCo: 100 ppm/C; Value_Code: 10k0; Value: 10.0k; EIA_Code: E96; Res_ohm: 10k; SizeX_mm: 1; SizeY_mm: 0.5; SizeZ_mm: 0.6; Value2: 0.063W; AEC Qualified: Y; VDC_V: 50V; AEC Category: Q200; AEC Grade: 0
R77-R79 = CMP-0120177-1: 2 mOhms ±1% 1W Chip Resistor Wide 1206 (3216 Metric), 0612 Anti-Sulfur, Automotive AEC-Q200, Current Sense, Moisture Resistant, Pulse Withstanding Metal Element; Manufacturer: Vishay; AEC Grade: Grade 0; AEC Qualified: Yes; Res_ohm: 2m; SizeZ_mm: 0.711mm; TempCo: 150ppm/°C; Value: 2m
R89 R91 R94 = CMP-0097004-1: PTCEL Series 500 V 60 Ohm ±30 % Radial Inrush Current Limiter PTC Thermistor; Manufacturer: Vishay Bccomponents; Value: 60Ω; SizeZ_mm: 17mm; AEC Qualified: Yes; Hold Current: 120mA; Tolerance_%: 30%; VDC_V: 500V; AEC Grade: Grade 2
R90 R92 R95 = CMP-0122581-1: 4.7 Ohms ±5% 3W Chip Resistor 2512 (6432 Metric) Automotive AEC-Q200 Thick Film; Manufacturer: Cal-Chip Electronics; AEC Grade: Grade 0; AEC Qualified: Yes; SizeZ_mm: 1.2mm; TempCo: 200ppm/°C; VDC_V: 250V
R96-R98 R100 = CMP-0096768-1: 5 kA Varistor 1 Circuit Through Hole Disc 17mm; Manufacturer: Bourns; AEC Qualified: No; SizeZ_mm: 23mm; VDC_V: 350V; Vc: 100A; ValueDisplayed: 40pF; Clamping Voltage: 730V
R104 = CMP-0026995-2: RES, 100 k, 5%, 0.1 W, AEC-Q200 Grade 0, 0402; Manufacturer: Panasonic; Power_W: 100mW; TempCo: 200 ppm/C; U/M: EA; Value: 100k; EIA_Code: E24; SizeX_mm: 1; SizeY_mm: 0.5; SizeZ_mm: 0.6; Value2: 0.1W; AEC Qualified: Y; VDC_V: 50V; AEC Grade: 0; AEC Category: Q200
R109 = CMP-0078244-2: RES, 30.0 k, 1%, 0.063 W, AEC-Q200 Grade 0, 0402; Manufacturer: Vishay-Dale; Power_W: 63mW; Green_Lifecycle: Active; TempCo: 100 ppm/C; Value_Code: 30k0; Green_REACh: Passed; Value: 30.0k; Res_ohm: 30k; SizeX_mm: 1; SizeY_mm: 0.5; SizeZ_mm: 0.6; Value2: 0.063W; AEC Qualified: Y; VDC_V: 50V; AEC Grade: 0; AEC Category: Q200
TP6 = CMP-0003825-1: 1mm Test Point, SMT; Manufacturer: Any
TP7 TP21 TP22 TP24 TP25 TP27 TP28 TP35-TP40 = CMP-0003968-1: Test Point, SMT; Manufacturer: Harwin
U10 = CMP-0120116-1: ±24 V Low Capacitance Surge Diode for Industrial Networks in SOT-23 Package; Manufacturer: Texas Instruments; SizeZ_mm: 1.12mm; AEC Qualified: No; Breakdown Voltage: 25.5V; Cap_F: 14pF; Clamping Voltage: 35V; Direction: Bidirectional; Ipp: 30A; Number Of Channels: 1; Ppk: 1200W; Standoff Height: 0.01mm; TaMax_C: +125°C; TaMin_C: -40°C; VRWM: 24V
U11 = CMP-0033793-2: Automotive 1.5-W, 12-V VIN / 12-VOUT, 15-V VIN / 15-V VOUT, HighDensity, > 5-kVRMS, Isolated DC/DC Module; Manufacturer: Texas Instruments; SizeZ_mm: 3.55mm; AEC Qualified: Yes; AEC Grade: Grade 1; Max Supply Voltage: 18V; Min Supply Voltage: 9V; Nominal Supply Current: 200-270mA; Number Of Outputs: 2; Output Type: AdjustableProgrammable; Output Voltage: 10-18V; Standoff Height: 0.1mm; Switching Frequency: 18MHz; TaMax_C: +125°C; TaMin_C: -40°C; TJmax_C: +150°C; AEC Category: Q200; CompType: IC
U12 = CMP-0095083-1: Manufacturer: Texas Instruments; SizeZ_mm: 1.1mm; Standoff Height: 0mm

## Sheet TIDA-1606-PCC-Current-Measurements-E7.SchDoc
size 431 x 279 mm; DocumentNumber: 7; SheetNumber: 7; SheetTotal: 16; PageSetup: Record=PageOptions¦CenterHorizontal=True¦CenterVertical=True¦PrintScale=1.00¦XCorrection=1.00¦YCorrection=1.00¦PrintKind=0¦BorderSize=5000000¦LeftOffset=0¦BottomOffset=0¦Orientation=2¦PaperLength=1000¦PaperWidth=1000¦Scale=100¦PaperSource=15¦PrintQuality=600¦MediaType=1¦DitherType=10¦PaperKind=Letter¦PrintScaleMode=1
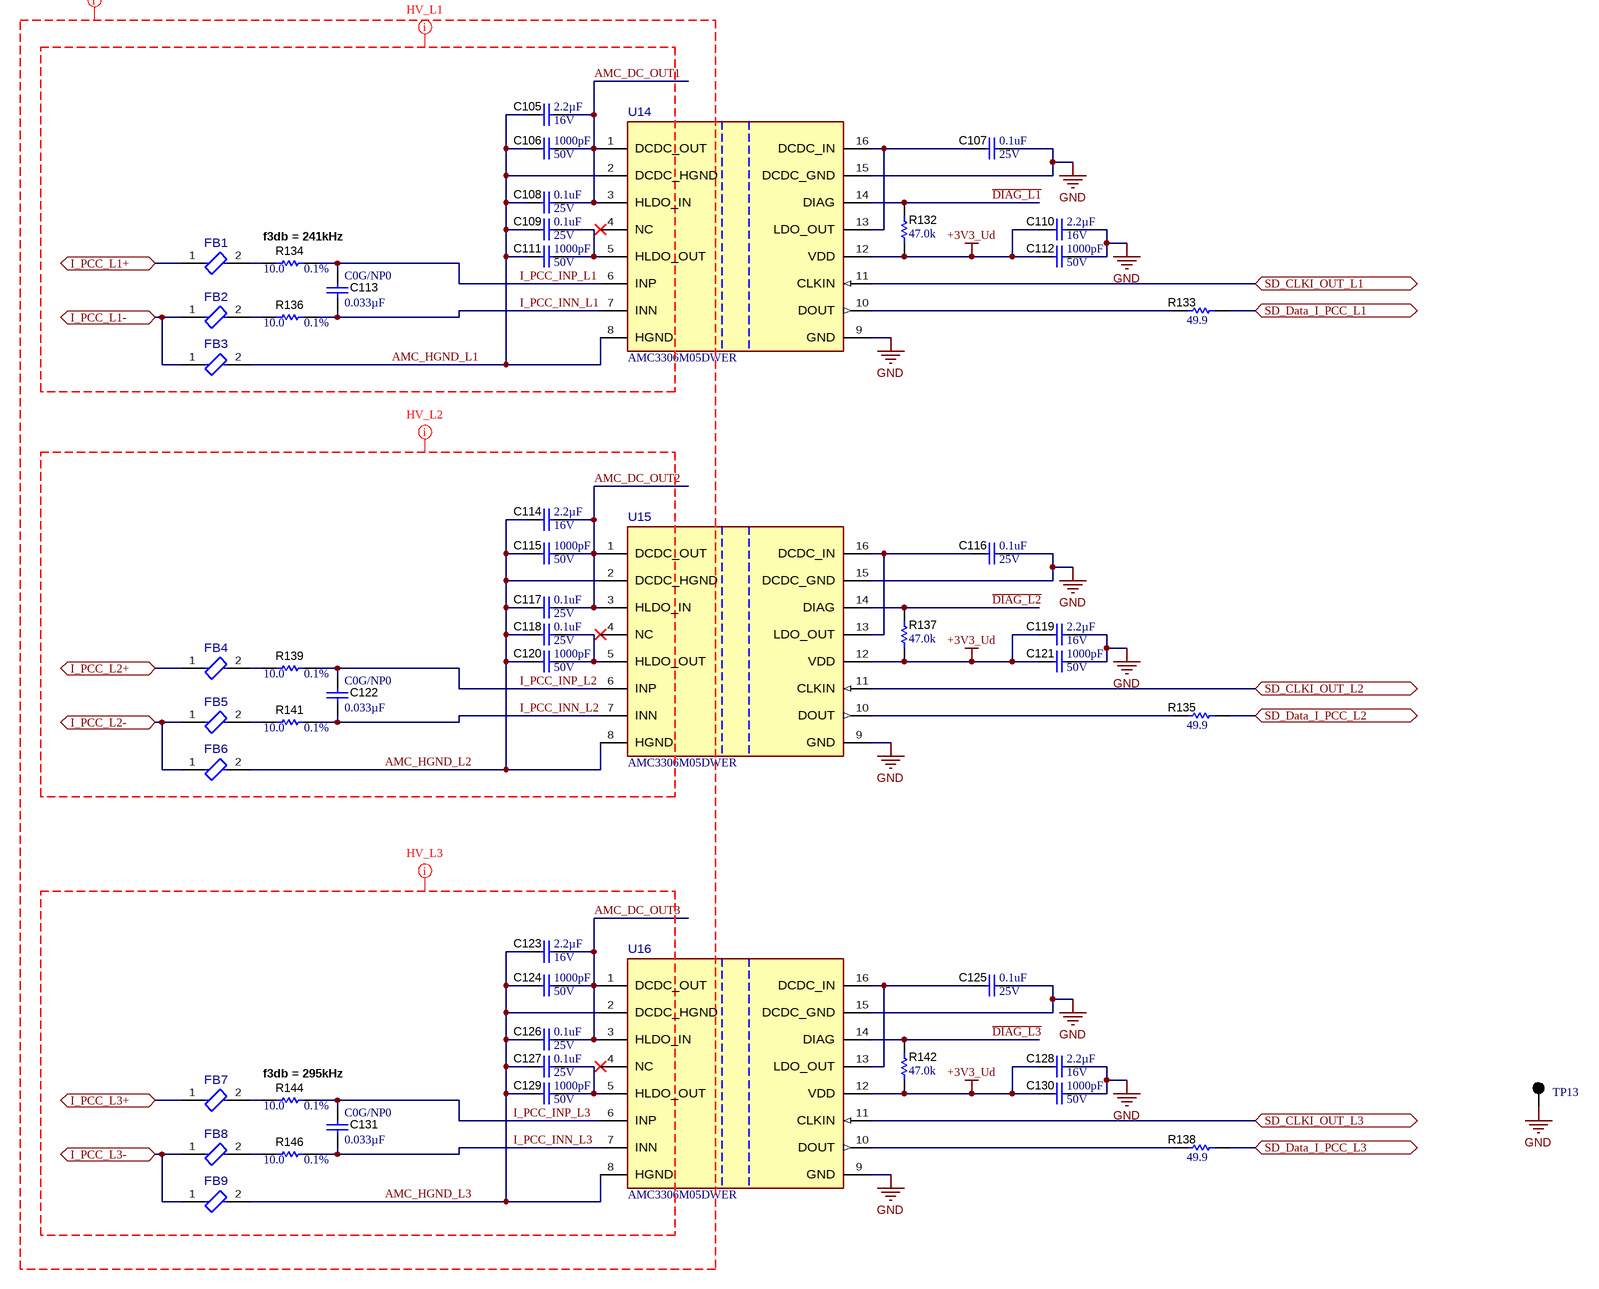
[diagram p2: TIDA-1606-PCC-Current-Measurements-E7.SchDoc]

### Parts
C105  Cap_F: 2.2µF  VDC_V: 16V  [0603]  (hidden comment: EMK107BB7225KA-T)
C106  VDC_V: 50V  ValueDisplayed: 1000pF  [0402L]  (hidden comment: GRM155R71H102KA01D)
C107  VDC_V: 25V  ValueDisplayed: 0.1uF  [0402L]  (hidden comment: GRM155R71E104KE14D)
C108  VDC_V: 25V  ValueDisplayed: 0.1uF  [0402L]  (hidden comment: GRM155R71E104KE14D)
C109  VDC_V: 25V  ValueDisplayed: 0.1uF  [0402L]  (hidden comment: GRM155R71E104KE14D)
C110  Cap_F: 2.2µF  VDC_V: 16V  [0603]  (hidden comment: EMK107BB7225KA-T)
C111  VDC_V: 50V  ValueDisplayed: 1000pF  [0402L]  (hidden comment: GRM155R71H102KA01D)
C112  VDC_V: 50V  ValueDisplayed: 1000pF  [0402]  (hidden comment: GRM155R71H102KA01D)
C113  TempCo: C0G/NP0  ValueDisplayed: 0.033µF  [0805_HV]  (hidden comment: CGA4J2C0G1H333J125AA)
C114  Cap_F: 2.2µF  VDC_V: 16V  [0603]  (hidden comment: EMK107BB7225KA-T)
C115  VDC_V: 50V  ValueDisplayed: 1000pF  [0402L]  (hidden comment: GRM155R71H102KA01D)
C116  VDC_V: 25V  ValueDisplayed: 0.1uF  [0402L]  (hidden comment: GRM155R71E104KE14D)
C117  VDC_V: 25V  ValueDisplayed: 0.1uF  [0402L]  (hidden comment: GRM155R71E104KE14D)
C118  VDC_V: 25V  ValueDisplayed: 0.1uF  [0402L]  (hidden comment: GRM155R71E104KE14D)
C119  Cap_F: 2.2µF  VDC_V: 16V  [0603]  (hidden comment: EMK107BB7225KA-T)
C120  VDC_V: 50V  ValueDisplayed: 1000pF  [0402L]  (hidden comment: GRM155R71H102KA01D)
C121  VDC_V: 50V  ValueDisplayed: 1000pF  [0402L]  (hidden comment: GRM155R71H102KA01D)
C122  TempCo: C0G/NP0  ValueDisplayed: 0.033µF  [0805_HV]  (hidden comment: CGA4J2C0G1H333J125AA)
C123  Cap_F: 2.2µF  VDC_V: 16V  [0603]  (hidden comment: EMK107BB7225KA-T)
C124  VDC_V: 50V  ValueDisplayed: 1000pF  [0402L]  (hidden comment: GRM155R71H102KA01D)
C125  VDC_V: 25V  ValueDisplayed: 0.1uF  [0402L]  (hidden comment: GRM155R71E104KE14D)
C126  VDC_V: 25V  ValueDisplayed: 0.1uF  [0402L]  (hidden comment: GRM155R71E104KE14D)
C127  VDC_V: 25V  ValueDisplayed: 0.1uF  [0402L]  (hidden comment: GRM155R71E104KE14D)
C128  Cap_F: 2.2µF  VDC_V: 16V  [0603]  (hidden comment: EMK107BB7225KA-T)
C129  VDC_V: 50V  ValueDisplayed: 1000pF  [0402L]  (hidden comment: GRM155R71H102KA01D)
C130  VDC_V: 50V  ValueDisplayed: 1000pF  [0402L]  (hidden comment: GRM155R71H102KA01D)
C131  TempCo: C0G/NP0  ValueDisplayed: 0.033µF  [0805_HV]  (hidden comment: CGA4J2C0G1H333J125AA)
FB1  74269244182  [FP-74269244182_0402-MFG]  (value not drawn)
FB2  74269244182  [FP-74269244182_0402-MFG]  (value not drawn)
FB3  74269244182  [FP-74269244182_0402-MFG]  (value not drawn)
FB4  74269244182  [FP-74269244182_0402-MFG]  (value not drawn)
FB5  74269244182  [FP-74269244182_0402-MFG]  (value not drawn)
FB6  74269244182  [FP-74269244182_0402-MFG]  (value not drawn)
FB7  74269244182  [FP-74269244182_0402-MFG]  (value not drawn)
FB8  74269244182  [FP-74269244182_0402-MFG]  (value not drawn)
FB9  74269244182  [FP-74269244182_0402-MFG]  (value not drawn)
R132  ValueDisplayed: 47.0k  [0402L]  (hidden comment: RC0402FR-0747KL)
R133  ValueDisplayed: 49.9  [0402L]  (hidden comment: ERJ-2RKF49R9X)
R134  Value1: 0.1%  ValueDisplayed: 10.0  [CPF0402]  (hidden comment: CPF0402B10RE1)
R135  ValueDisplayed: 49.9  [0402L]  (hidden comment: ERJ-2RKF49R9X)
R136  Value1: 0.1%  ValueDisplayed: 10.0  [CPF0402]  (hidden comment: CPF0402B10RE1)
R137  ValueDisplayed: 47.0k  [0402L]  (hidden comment: RC0402FR-0747KL)
R138  ValueDisplayed: 49.9  [0402L]  (hidden comment: ERJ-2RKF49R9X)
R139  Value1: 0.1%  ValueDisplayed: 10.0  [CPF0402]  (hidden comment: CPF0402B10RE1)
R141  Value1: 0.1%  ValueDisplayed: 10.0  [CPF0402]  (hidden comment: CPF0402B10RE1)
R142  ValueDisplayed: 47.0k  [0402L]  (hidden comment: RC0402FR-0747KL)
R144  Value1: 0.1%  ValueDisplayed: 10.0  [CPF0402]  (hidden comment: CPF0402B10RE1)
R146  Value1: 0.1%  ValueDisplayed: 10.0  [CPF0402]  (hidden comment: CPF0402B10RE1)
TP13  5011  [Keystone5011]  (value not drawn)
U14  AMC3306M05DWER  [DWE0016A-MFG]
U15  AMC3306M05DWER  [DWE0016A-MFG]
U16  AMC3306M05DWER  [DWE0016A-MFG]

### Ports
I_PCC_L1+ (bidir), I_PCC_L1- (bidir), I_PCC_L2+ (bidir), I_PCC_L2- (bidir), I_PCC_L3+ (bidir), I_PCC_L3- (bidir), SD_CLKI_OUT_L1 (bidir), SD_CLKI_OUT_L2 (bidir), SD_CLKI_OUT_L3 (bidir), SD_Data_I_PCC_L1 (bidir), SD_Data_I_PCC_L2 (bidir), SD_Data_I_PCC_L3 (bidir)

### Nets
+3V3_Ud: C110.1 C112.2 C119.1 C121.2 C128.1 C130.2 R132.1 R137.1 R142.1 U14.12(VDD) U15.12(VDD) U16.12(VDD)
GND: C107.1 C110.2 C112.1 C116.1 C119.2 C121.1 C125.1 C128.2 C130.1 TP13.1 U14.9(GND) U14.15(DCDC_GND) U15.9(GND) U15.15(DCDC_GND) U16.9(GND) U16.15(DCDC_GND)
~{DIAG_L1}: R132.2 U14.14(DIAG)
~{DIAG_L2}: R137.2 U15.14(DIAG)
~{DIAG_L3}: R142.2 U16.14(DIAG)
AMC_DC_OUT1: C105.2 C106.1 C108.1 U14.1(DCDC_OUT) U14.3(HLDO_IN)
AMC_DC_OUT2: C114.2 C115.1 C117.1 U15.1(DCDC_OUT) U15.3(HLDO_IN)
AMC_DC_OUT3: C123.2 C124.1 C126.1 U16.1(DCDC_OUT) U16.3(HLDO_IN)
AMC_HGND_L1: C105.1 C106.2 C108.2 C109.2 C111.2 FB3.2 U14.2(DCDC_HGND) U14.8(HGND)
AMC_HGND_L2: C114.1 C115.2 C117.2 C118.2 C120.2 FB6.2 U15.2(DCDC_HGND) U15.8(HGND)
AMC_HGND_L3: C123.1 C124.2 C126.2 C127.2 C129.2 FB9.2 U16.2(DCDC_HGND) U16.8(HGND)
I_PCC_INN_L1: C113.2 R136.2 U14.7(INN)
I_PCC_INN_L2: C122.2 R141.2 U15.7(INN)
I_PCC_INN_L3: C131.2 R146.2 U16.7(INN)
I_PCC_INP_L1: C113.1 R134.2 U14.6(INP)
I_PCC_INP_L2: C122.1 R139.2 U15.6(INP)
I_PCC_INP_L3: C131.1 R144.2 U16.6(INP)
I_PCC_L1+: FB1.1 ; port I_PCC_L1+
I_PCC_L1-: FB2.1 FB3.1 ; port I_PCC_L1-
I_PCC_L2+: FB4.1 ; port I_PCC_L2+
I_PCC_L2-: FB5.1 FB6.1 ; port I_PCC_L2-
I_PCC_L3+: FB7.1 ; port I_PCC_L3+
I_PCC_L3-: FB8.1 FB9.1 ; port I_PCC_L3-
SD_CLKI_OUT_L1: U14.11(CLKIN) ; port SD_CLKI_OUT_L1
SD_CLKI_OUT_L2: U15.11(CLKIN) ; port SD_CLKI_OUT_L2
SD_CLKI_OUT_L3: U16.11(CLKIN) ; port SD_CLKI_OUT_L3
SD_Data_I_PCC_L1: R133.2 ; port SD_Data_I_PCC_L1
SD_Data_I_PCC_L2: R135.2 ; port SD_Data_I_PCC_L2
SD_Data_I_PCC_L3: R138.2 ; port SD_Data_I_PCC_L3
NetC107_2: C107.2 U14.13(LDO_OUT) U14.16(DCDC_IN)
NetC109_1: C109.1 C111.1 U14.5(HLDO_OUT)
NetC116_2: C116.2 U15.13(LDO_OUT) U15.16(DCDC_IN)
NetC118_1: C118.1 C120.1 U15.5(HLDO_OUT)
NetC125_2: C125.2 U16.13(LDO_OUT) U16.16(DCDC_IN)
NetC127_1: C127.1 C129.1 U16.5(HLDO_OUT)
NetFB1_2: FB1.2 R134.1
NetFB2_2: FB2.2 R136.1
NetFB4_2: FB4.2 R139.1
NetFB5_2: FB5.2 R141.1
NetFB7_2: FB7.2 R144.1
NetFB8_2: FB8.2 R146.1
NetR133_1: R133.1 U14.10(DOUT)
NetR135_1: R135.1 U15.10(DOUT)
NetR138_1: R138.1 U16.10(DOUT)

Not connected (* = marked no-connect by the designer): U14 4(NC)*; U15 4(NC)*; U16 4(NC)*

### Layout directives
net class HV_L1: AMC_DC_OUT1, AMC_HGND_L1, I_PCC_INN_L1, I_PCC_INP_L1
net class HV_L2: AMC_DC_OUT2, AMC_HGND_L2, I_PCC_INN_L2, I_PCC_INP_L2
net class HV_L3: AMC_DC_OUT3, AMC_HGND_L3, I_PCC_INN_L3, I_PCC_INP_L3
net class HV_AC1: AMC_DC_OUT1, AMC_DC_OUT2, AMC_DC_OUT3, AMC_HGND_L1, AMC_HGND_L2, AMC_HGND_L3, I_PCC_INN_L1, I_PCC_INN_L2, I_PCC_INN_L3, I_PCC_INP_L1, I_PCC_INP_L2, I_PCC_INP_L3

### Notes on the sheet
- (near R134) f3db = 241kHz
- (near R144) f3db = 295kHz

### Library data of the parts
C105 C110 C114 C119 C123 C128 = CMP-0007121-4: CAP, CERM, 2.2 uF, 16 V, +/- 10%, X7R, 0603; Manufacturer: Taiyo Yuden; TaMin_C: -55°C; Polarized: N; SizeAreaWB_mm2: 4.68; Value1: Unknown; U/M: EA; Value: 2.2uF; TaMax_C: 125°C; SizeZ_mm: 1; SizeX_mm: 1.6; SizeY_mm: 0.8; SizeArea_mm2: 1.28; AEC Category: Q200
C106 C111 C115 C120 C121 C124 C129 C130 = CMP-0006673-2: CAP, CERM, 1000 pF, 50 V, +/- 10%, X7R, 0402; Manufacturer: MuRata; TaMin_C: -55°C; Polarized: N; SizeAreaWB_mm2: 3; Value1: Unknown; U/M: EA; Value: 1000pF; TaMax_C: 125°C; SizeZ_mm: 0.6; SizeX_mm: 1; SizeY_mm: 0.5; Cap_Case: 0402; Cap_F: 1nF; AEC Category: Q200
C107-C109 C116-C118 C125-C127 = CMP-0006659-2: as C92 on sheet TIDA-1606-EMI-Protection-E7-
C112 = CMP-0006673-2: CAP, CERM, 1000 pF, 50 V, +/- 10%, X7R, 0402; Manufacturer: MuRata; TaMin_C: -55°C; Polarized: N; SizeAreaWB_mm2: 3; Value1: Unknown; U/M: EA; Value: 1000pF; TaMax_C: 125°C; SizeZ_mm: 0.6; SizeX_mm: 1; SizeY_mm: 0.5; Cap_F: 1nF; AEC Category: Q200
C113 C122 C131 = CMP-0080742-1: CAP, CERM, 0.033 µF, 50 V,+/- 5%, C0G/NP0, AEC-Q200 Grade 1, 0805; Manufacturer: TDK; Cap_F: 33nF; SizeAreaWB_mm2: 6.75; SizeArea_mm2: 2.5; AEC Qualified: Y; AEC Category: Q200; Value: 0.033uF; TaMax_C: 125°C; SizeZ_mm: 1.45; AEC Grade: 1; Polarized: N; TaMin_C: -55°C; VDC_V: 50V; SizeY_mm: 1.25; U/M: EA; SizeX_mm: 2; Cap_Case: 0805
FB1-FB9 = CMP-0091663-1: 1.8 kOhms @ 100MHz 1 Power, Signal Line Ferrite Bead 0402 (1005 Metric) 210mA 2.1Ohm; Manufacturer: Wurth Electronics; SizeZ_mm: 0.55mm; AEC Qualified: No; DCR_ohm: 2.1; Tolerance_%: 25%; Test Frequency: 1GHz; Impedance At Frequency: 1800Ω @ 100MHz
R132 R137 R142 = CMP-0026737-1: RES, 47.0 k, 1%, 0.0625 W, 0402; Manufacturer: Yageo America; Power_W: 62.5mW; TempCo: 100 ppm/C; Value_Code: 47k0; U/M: EA; Value: 47.0k; Res_ohm: 47k; SizeX_mm: 1; SizeY_mm: 0.5; SizeZ_mm: 0.6; AEC Qualified: N; VDC_V: 50V; AEC Category: Q200
R133 R135 R138 = CMP-0026703-1: as R66 on sheet TIDA-1606-EMI-Protection-E7-
R134 R136 R139 R141 R144 R146 = CMP-0026765-1: RES, 10.0, 0.1%, 0.063 W, 0402; Manufacturer: TE Connectivity; Power_W: 63mW; TempCo: 25 ppm/C; Value_Code: 10R0; U/M: EA; Value: 10.0; EIA_Code: E192; Res_ohm: 10; SizeX_mm: 1; SizeY_mm: 0.5; SizeZ_mm: 0.35; Value2: 0.063W; AEC Qualified: N; AEC Category: Q200
TP13 = CMP-0055148-2: Test Point, Multipurpose, Black, TH; Manufacturer: Keystone Electronics; CNHeader: FALSE; ContactFinish: Silver; Green_REACh: Passed; Green_Lifecycle: Active; CT: TRUE
U14-U16 = CMP-0121159-1: High-precision, ±50-mV input, reinforced isolated modulator with integrated DC/DC converter 16-SOIC -40 to 125; Manufacturer: Texas Instruments; SizeZ_mm: 2.65mm; AEC Qualified: No; Data Polarity: Differential; Interface: SPI; Max Supply Voltage: 5.5V; Min Supply Voltage: 3V; Nominal Supply Current: 26-28mA; Number Of Channels: 1; Resolution: 16bits; Sampling Rate: 78ksps; Standoff Height: 0.1mm; TaMax_C: +125°C; TaMin_C: -40°C; TJmax_C: +150°C

## Sheet TIDA-1606-PCC-Voltage-Measurements-E7.SchDoc
size A3; Date: Not shown in title block; ApprovedBy: Not shown in title block; CheckedBy: Not shown in title block; Author: Not shown in title block; CompanyName: Not shown in title block; Engineer: Not shown in title block; Organization: Not shown in title block; Address1: Not shown in title block; Address2: Not shown in title block; Address3: Not shown in title block; Address4: Not shown in title block; DocumentNumber: 5; Revision: Use project parameter SCH_Rev; SheetNumber: 5; SheetTotal: 16; PageSetup: Record=PageOptions¦CenterHorizontal=True¦CenterVertical=True¦PrintScale=0.69¦XCorrection=1.00¦YCorrection=1.00¦PrintKind=0¦BorderSize=5000000¦LeftOffset=0¦BottomOffset=0¦Orientation=2¦PaperLength=1000¦PaperWidth=1000¦Scale=100¦PaperSource=15¦PrintQuality=600¦MediaType=1¦DitherType=10¦PaperKind=Letter¦PrintScaleMode=1
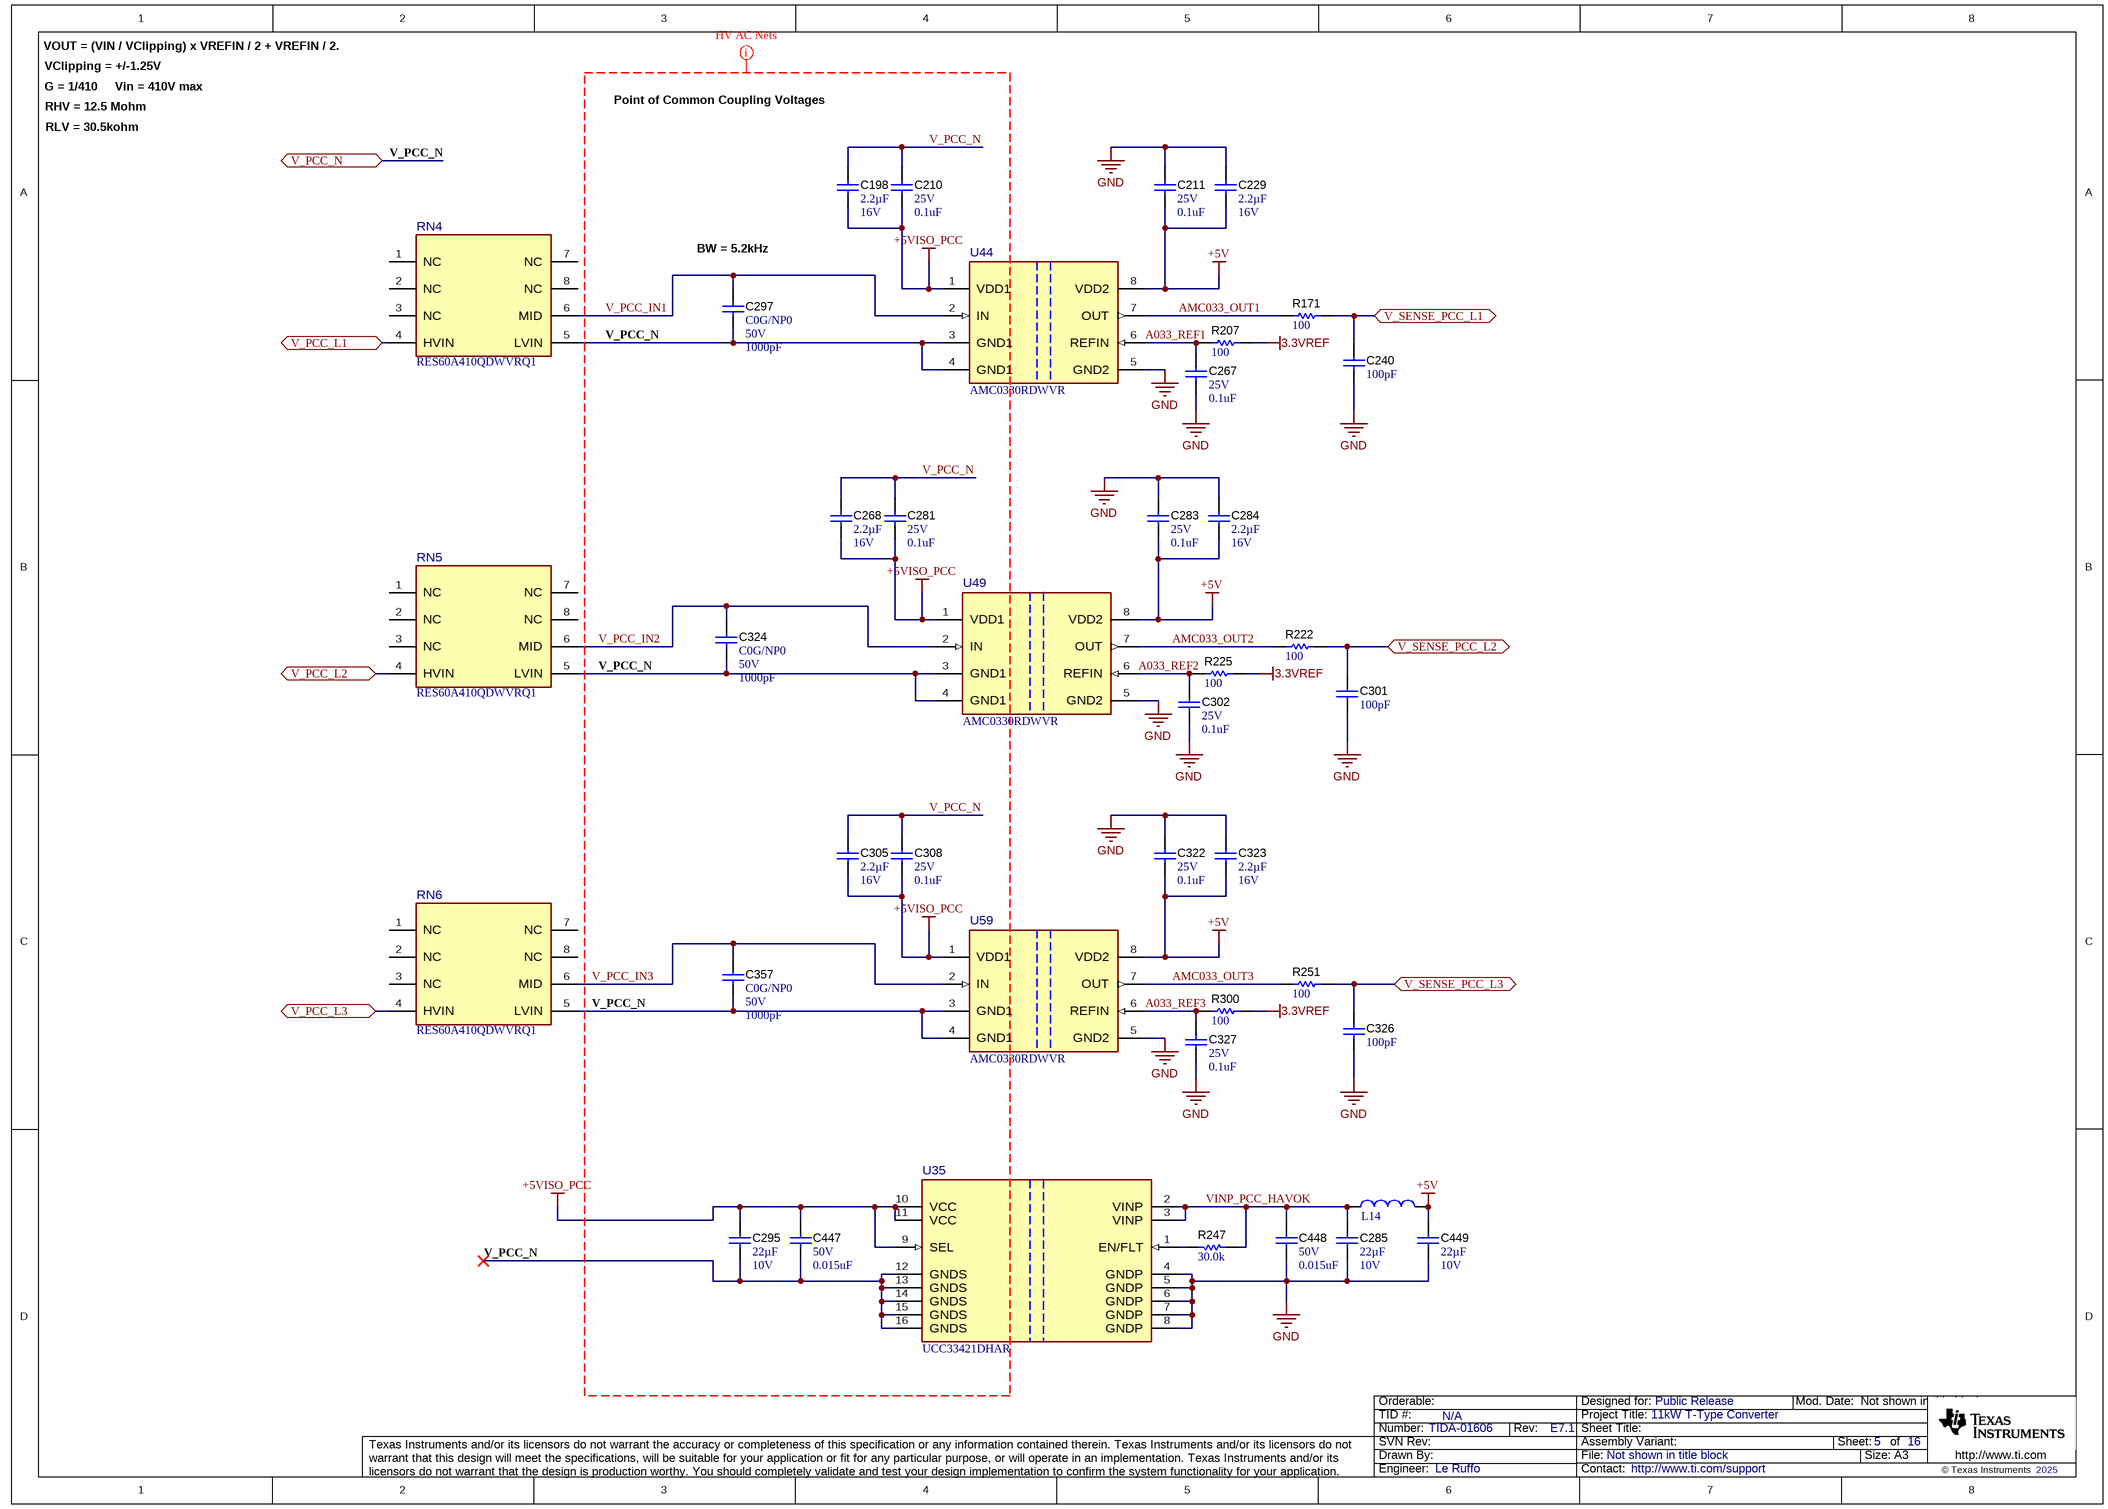
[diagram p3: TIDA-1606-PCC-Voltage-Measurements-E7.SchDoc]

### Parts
C198  Cap_F: 2.2µF  VDC_V: 16V  [0603]  (hidden comment: EMK107BB7225KA-T)
C210  VDC_V: 25V  ValueDisplayed: 0.1uF  [0402L]  (hidden comment: GRM155R71E104KE14D)
C211  VDC_V: 25V  ValueDisplayed: 0.1uF  [0402L]  (hidden comment: GRM155R71E104KE14D)
C229  Cap_F: 2.2µF  VDC_V: 16V  [0603]  (hidden comment: EMK107BB7225KA-T)
C240  ValueDisplayed: 100pF  [0402L]  (hidden comment: GRM1555C1H101JA01D)
C267  VDC_V: 25V  ValueDisplayed: 0.1uF  [0402L]  (hidden comment: GRM155R71E104KE14D)
C268  Cap_F: 2.2µF  VDC_V: 16V  [0603]  (hidden comment: EMK107BB7225KA-T)
C281  VDC_V: 25V  ValueDisplayed: 0.1uF  [0402L]  (hidden comment: GRM155R71E104KE14D)
C283  VDC_V: 25V  ValueDisplayed: 0.1uF  [0402L]  (hidden comment: GRM155R71E104KE14D)
C284  Cap_F: 2.2µF  VDC_V: 16V  [0603]  (hidden comment: EMK107BB7225KA-T)
C285  Cap_F: 22µF  VDC_V: 10V  [0805_HV]  (hidden comment: GRM21BZ71A226ME15L)
C295  Cap_F: 22µF  VDC_V: 10V  [0805_HV]  (hidden comment: GRM21BZ71A226ME15L)
C297  TempCo: C0G/NP0  VDC_V: 50V  ValueDisplayed: 1000pF  [0402L]  (hidden comment: CGA2B2C0G1H102J050BA)
C301  ValueDisplayed: 100pF  [0402L]  (hidden comment: GRM1555C1H101JA01D)
C302  VDC_V: 25V  ValueDisplayed: 0.1uF  [0402L]  (hidden comment: GRM155R71E104KE14D)
C305  Cap_F: 2.2µF  VDC_V: 16V  [0603]  (hidden comment: EMK107BB7225KA-T)
C308  VDC_V: 25V  ValueDisplayed: 0.1uF  [0402L]  (hidden comment: GRM155R71E104KE14D)
C322  VDC_V: 25V  ValueDisplayed: 0.1uF  [0402L]  (hidden comment: GRM155R71E104KE14D)
C323  Cap_F: 2.2µF  VDC_V: 16V  [0603]  (hidden comment: EMK107BB7225KA-T)
C324  TempCo: C0G/NP0  VDC_V: 50V  ValueDisplayed: 1000pF  [0402L]  (hidden comment: CGA2B2C0G1H102J050BA)
C326  ValueDisplayed: 100pF  [0402L]  (hidden comment: GRM1555C1H101JA01D)
C327  VDC_V: 25V  ValueDisplayed: 0.1uF  [0402L]  (hidden comment: GRM155R71E104KE14D)
C357  TempCo: C0G/NP0  VDC_V: 50V  ValueDisplayed: 1000pF  [0402L]  (hidden comment: CGA2B2C0G1H102J050BA)
C447  VDC_V: 50V  ValueDisplayed: 0.015uF  [0402L]  (hidden comment: CGA2B3X7R1H153K050BB)
C448  VDC_V: 50V  ValueDisplayed: 0.015uF  [0402L]  (hidden comment: CGA2B3X7R1H153K050BB)
C449  Cap_F: 22µF  VDC_V: 10V  [0805_HV]  (hidden comment: GRM21BZ71A226ME15L)
L14  74479763222  [WE-PMI_0603_L1.6W0.8H0.8]  (value not drawn)
R171  ValueDisplayed: 100  [0402L]  (hidden comment: ERJ-2RKF1000X)
R207  ValueDisplayed: 100  [0402L]  (hidden comment: ERJ-2RKF1000X)
R222  ValueDisplayed: 100  [0402L]  (hidden comment: ERJ-2RKF1000X)
R225  ValueDisplayed: 100  [0402L]  (hidden comment: ERJ-2RKF1000X)
R247  ValueDisplayed: 30.0k  [0402L]  (hidden comment: CRCW040230K0FKED)
R251  ValueDisplayed: 100  [0402L]  (hidden comment: ERJ-2RKF1000X)
R300  ValueDisplayed: 100  [0402L]  (hidden comment: ERJ-2RKF1000X)
RN4  RES60A410QDWVRQ1  [DWV0008A-MFG]
RN5  RES60A410QDWVRQ1  [DWV0008A-MFG]
RN6  RES60A410QDWVRQ1  [DWV0008A-MFG]
U35  UCC33421DHAR  [DHA0016A-MFG]
U44  AMC0330RDWVR  [DWV0008A-MFG]
U49  AMC0330RDWVR  [DWV0008A-MFG]
U59  AMC0330RDWVR  [DWV0008A-MFG]

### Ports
V_PCC_L1 (bidir), V_PCC_L2 (bidir), V_PCC_L3 (bidir), V_PCC_N (bidir), V_SENSE_PCC_L1 (bidir), V_SENSE_PCC_L2 (bidir), V_SENSE_PCC_L3 (bidir)

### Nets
3.3VREF: R207.2 R225.2 R300.2
+5V: C211.2 C229.1 C283.2 C284.1 C322.2 C323.1 C449.1 L14.2 U44.8(VDD2) U49.8(VDD2) U59.8(VDD2)
+5VISO_PCC: C198.1 C210.2 C268.1 C281.2 C295.1 C305.1 C308.2 C447.1 U35.9(SEL) U35.10(VCC) U35.11(VCC) U44.1(VDD1) U49.1(VDD1) U59.1(VDD1)
GND: C211.1 C229.2 C240.2 C267.2 C283.1 C284.2 C285.2 C301.2 C302.2 C322.1 C323.2 C326.2 C327.2 C448.2 C449.2 U35.4(GNDP) U35.5(GNDP) U35.6(GNDP) U35.7(GNDP) U35.8(GNDP) U44.5(GND2) U49.5(GND2) U59.5(GND2)
A033_REF1: C267.1 R207.1 U44.6(REFIN)
A033_REF2: C302.1 R225.1 U49.6(REFIN)
A033_REF3: C327.1 R300.1 U59.6(REFIN)
AMC033_OUT1: R171.1 U44.7(OUT)
AMC033_OUT2: R222.1 U49.7(OUT)
AMC033_OUT3: R251.1 U59.7(OUT)
V_PCC_IN1: C297.1 RN4.6(MID) U44.2(IN)
V_PCC_IN2: C324.1 RN5.6(MID) U49.2(IN)
V_PCC_IN3: C357.1 RN6.6(MID) U59.2(IN)
V_PCC_L1: RN4.4(HVIN) ; port V_PCC_L1
V_PCC_L2: RN5.4(HVIN) ; port V_PCC_L2
V_PCC_L3: RN6.4(HVIN) ; port V_PCC_L3
V_PCC_N: C198.2 C210.1 C268.2 C281.1 C295.2 C297.2 C305.2 C308.1 C324.2 C357.2 C447.2 RN4.5(LVIN) RN5.5(LVIN) RN6.5(LVIN) U35.12(GNDS) U35.13(GNDS) U35.14(GNDS) U35.15(GNDS) U35.16(GNDS) U44.3(GND1) U44.4(GND1) U49.3(GND1) U49.4(GND1) U59.3(GND1) U59.4(GND1) ; port V_PCC_N
V_SENSE_PCC_L1: C240.1 R171.2 ; port V_SENSE_PCC_L1
V_SENSE_PCC_L2: C301.1 R222.2 ; port V_SENSE_PCC_L2
V_SENSE_PCC_L3: C326.1 R251.2 ; port V_SENSE_PCC_L3
VINP_PCC_HAVOK: C285.1 C448.1 L14.1 R247.1 U35.2(VINP) U35.3(VINP)
NetR247_2: R247.2 U35.1(EN/FLT)

Not connected (* = marked no-connect by the designer): RN4 1(NC) 2(NC) 3(NC) 7(NC) 8(NC); RN5 1(NC) 2(NC) 3(NC) 7(NC) 8(NC); RN6 1(NC) 2(NC) 3(NC) 7(NC) 8(NC)

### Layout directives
net class HV_AC1; net class HV_VSEN_PCC: +5VISO_PCC, V_PCC_IN1, V_PCC_IN2, V_PCC_IN3, V_PCC_N

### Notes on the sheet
- VOUT = (VIN / VClipping) x VREFIN / 2 + VREFIN / 2.
- G = 1/410
- RHV = 12.5 Mohm
- VClipping = +/-1.25V
- Vin = 410V max
- Point of Common Coupling Voltages
- RLV = 30.5kohm
- (near C297) BW = 5.2kHz

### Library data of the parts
C198 C229 C268 C284 C305 C323 = CMP-0007121-4: as C105 on sheet TIDA-1606-PCC-Current-Measurements-E7
C210 C211 C267 C281 C283 C302 C308 C322 C327 = CMP-0006659-2: as C92 on sheet TIDA-1606-EMI-Protection-E7-
C240 C301 C326 = CMP-0006410-2: CAP, CERM, 100 pF, 50 V, +/- 5%, C0G/NP0, 0402; Manufacturer: MuRata; TaMin_C: -55°C; Polarized: N; SizeAreaWB_mm2: 3; Value1: Unknown; U/M: EA; Value: 100pF; TaMax_C: 125°C; SizeZ_mm: 0.6; SizeX_mm: 1; SizeY_mm: 0.5; Cap_Case: 0402; Value2: 50V; AEC Category: Q200
C285 C295 C449 = CMP-0008377-2: CAP, CERM, 22 uF, 10 V, +/- 20%, X7R, 0805; Manufacturer: MuRata; SizeY_mm: 1.25; Cap_Case: 0805; SizeArea_mm2: 2.5; AEC Qualified: N; AEC Category: Q200; ValueDisplayed: 22uF; TaMin_C: -55°C; SizeAreaWB_mm2: 6.75; Value1: Unknown; U/M: EA; Value: 22uF; TaMax_C: 125°C; SizeZ_mm: 1.45; SizeX_mm: 2
C297 C324 C357 = CMP-0006309-2: CAP, CERM, 1000 pF, 50 V, +/- 5%, C0G/NP0, AEC-Q200 Grade 1, 0402; Manufacturer: TDK; TaMin_C: -55°C; Polarized: N; SizeAreaWB_mm2: 3; Value1: Unknown; U/M: EA; Value: 1000pF; TaMax_C: 125°C; SizeZ_mm: 0.6; SizeX_mm: 1; SizeY_mm: 0.5; Cap_Case: 0402; AEC Qualified: Y; Cap_F: 1nF; AEC Category: Q200
C447 C448 = CMP-0006327-2: CAP, CERM, 0.015 uF, 50 V, +/- 10%, X7R, AEC-Q200 Grade 1, 0402; Manufacturer: TDK; TaMin_C: -55°C; ESR_ohm: 0.2162; Polarized: N; SizeAreaWB_mm2: 3; Value1: 0.2162 ohm; U/M: EA; TaMax_C: 125°C; SizeZ_mm: 0.6; SizeX_mm: 1; SizeY_mm: 0.5; Cap_Case: 0402; AEC Qualified: Y; Cap_F: 15nF; IRMS_A: 379.389mA; AEC Category: Q200
L14 = CMP-0100992-1: WE-PMI SMT Power Multilayer Inductor, size 0603, 2.2uH, 0.8A, 375mOhm; Manufacturer: Wurth Elektronik; Case/Size Code: 0603; Inductance Tolerance: 20%; Q Factor: 15; Saturation Current: 0.28A; Self Resonant Frequency: 80MHz; Type: Low RDC
R171 R207 R222 R225 R251 R300 = CMP-0026656-1: RES, 100, 1%, 0.1 W, 0402; Manufacturer: Panasonic; Power_W: 100mW; TempCo: 100 ppm/C; Value_Code: 100R; U/M: EA; Value: 100; EIA_Code: E96; SizeX_mm: 1; SizeY_mm: 0.5; SizeZ_mm: 0.6; Value2: 0.1W; VDC_V: 50V; AEC Category: Q200
R247 = CMP-0078244-2: as R109 on sheet TIDA-1606-EMI-Protection-E7-
RN4-RN6 = CMP-0122946-1: Automotive, 1700-V, Precision Resistive Divider; Manufacturer: Texas Instruments; SizeZ_mm: 2.8mm; AEC Qualified: Yes; AEC Grade: Grade 1; Number Of Resistors: 2; Standoff Height: 0.36mm; TaMax_C: +125°C; TaMin_C: -40°C; TempCo: 1ppm/°C; TJmax_C: +150°C; Tolerance_%: 0.05%; VDC_V: 1700V
U35 = CMP-0123146-1: Ultra-Small, 1.5W, 5.0V, 5kVRMS Isolation, Industrial DC/DC Module; Manufacturer: Texas Instruments; SizeZ_mm: 2.6mm; AEC Qualified: No; Max Supply Voltage: 5.5V; Min Supply Voltage: 4.5V; Nominal Supply Current: 7-545mA; Number Of Outputs: 1; Output Type: AdjustableProgrammable; Output Voltage: 5/5.5V; Standoff Height: 0.1mm; Switching Frequency: 76MHz; Switching Topology: Boost; TaMax_C: +125°C; TaMin_C: -40°C; TJmax_C: +150°C
U44 U49 U59 = CMP-0122725-1: Automotive, Precision, ±1V Input Isolated Amplifiers With Single-Ended, Ratiometric Output; Manufacturer: Texas Instruments; SizeZ_mm: 2.8mm; AEC Qualified: Yes; AEC Grade: Grade 1; Bandwidth: 110kHz; Input Bias Current: 0.0035uA; Input Offset Voltage: 0.4mV; Max Supply Voltage: 5.5V; Min Supply Voltage: 3V; Number Of Channels: 1; Output Current Per Channel: 14mA; Response Time: 500us; Standoff Height: 0.36mm; TaMax_C: +125°C; TaMin_C: -40°C; TJmax_C: +150°C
